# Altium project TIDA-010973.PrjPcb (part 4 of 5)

## Sheet TIDA-010973_JTAG_UART.SchDoc
size 558 x 431 mm; Date: Not shown in title block; ApprovedBy: Not shown in title block; CheckedBy: Not shown in title block; Author: Not shown in title block; CompanyName: Not shown in title block; Engineer: Not shown in title block; Organization: Not shown in title block; Address1: Not shown in title block; Address2: Not shown in title block; Address3: Not shown in title block; Address4: Not shown in title block; DocumentNumber: 2; Revision: Use project parameter SCH_Rev; SheetNumber: 14; SheetTotal: 15
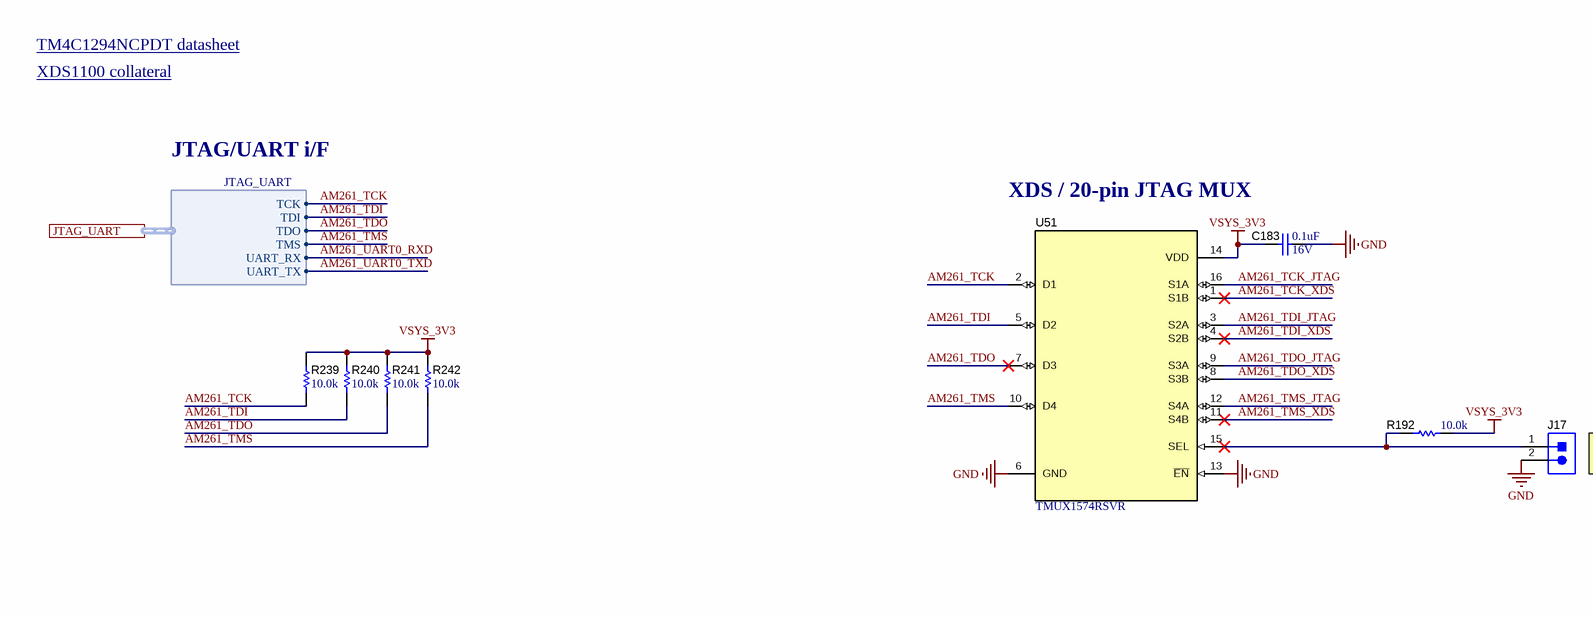
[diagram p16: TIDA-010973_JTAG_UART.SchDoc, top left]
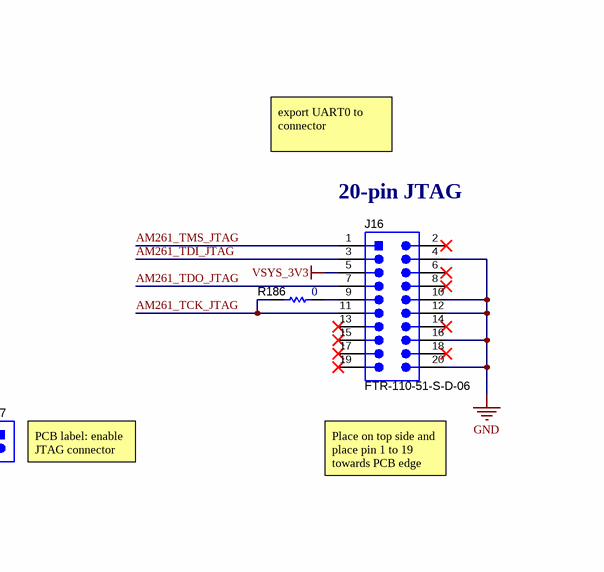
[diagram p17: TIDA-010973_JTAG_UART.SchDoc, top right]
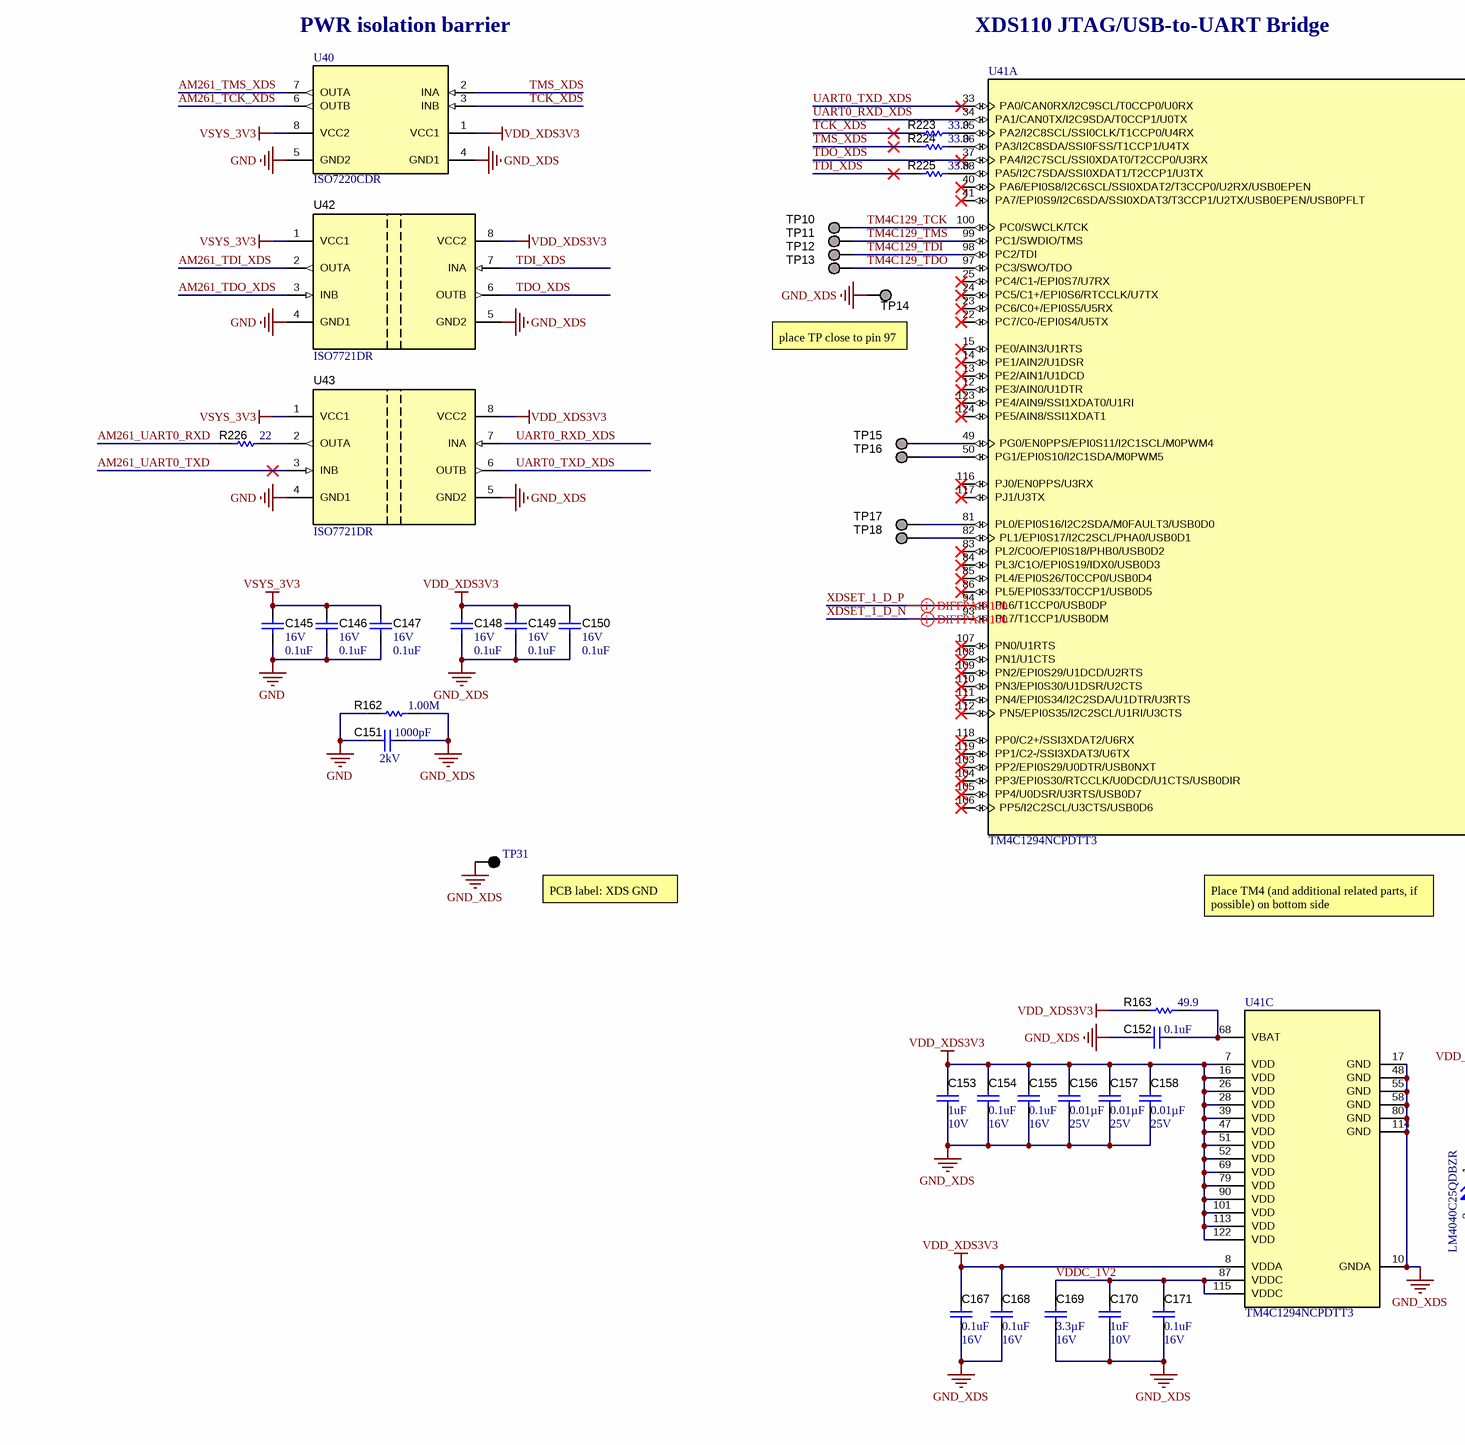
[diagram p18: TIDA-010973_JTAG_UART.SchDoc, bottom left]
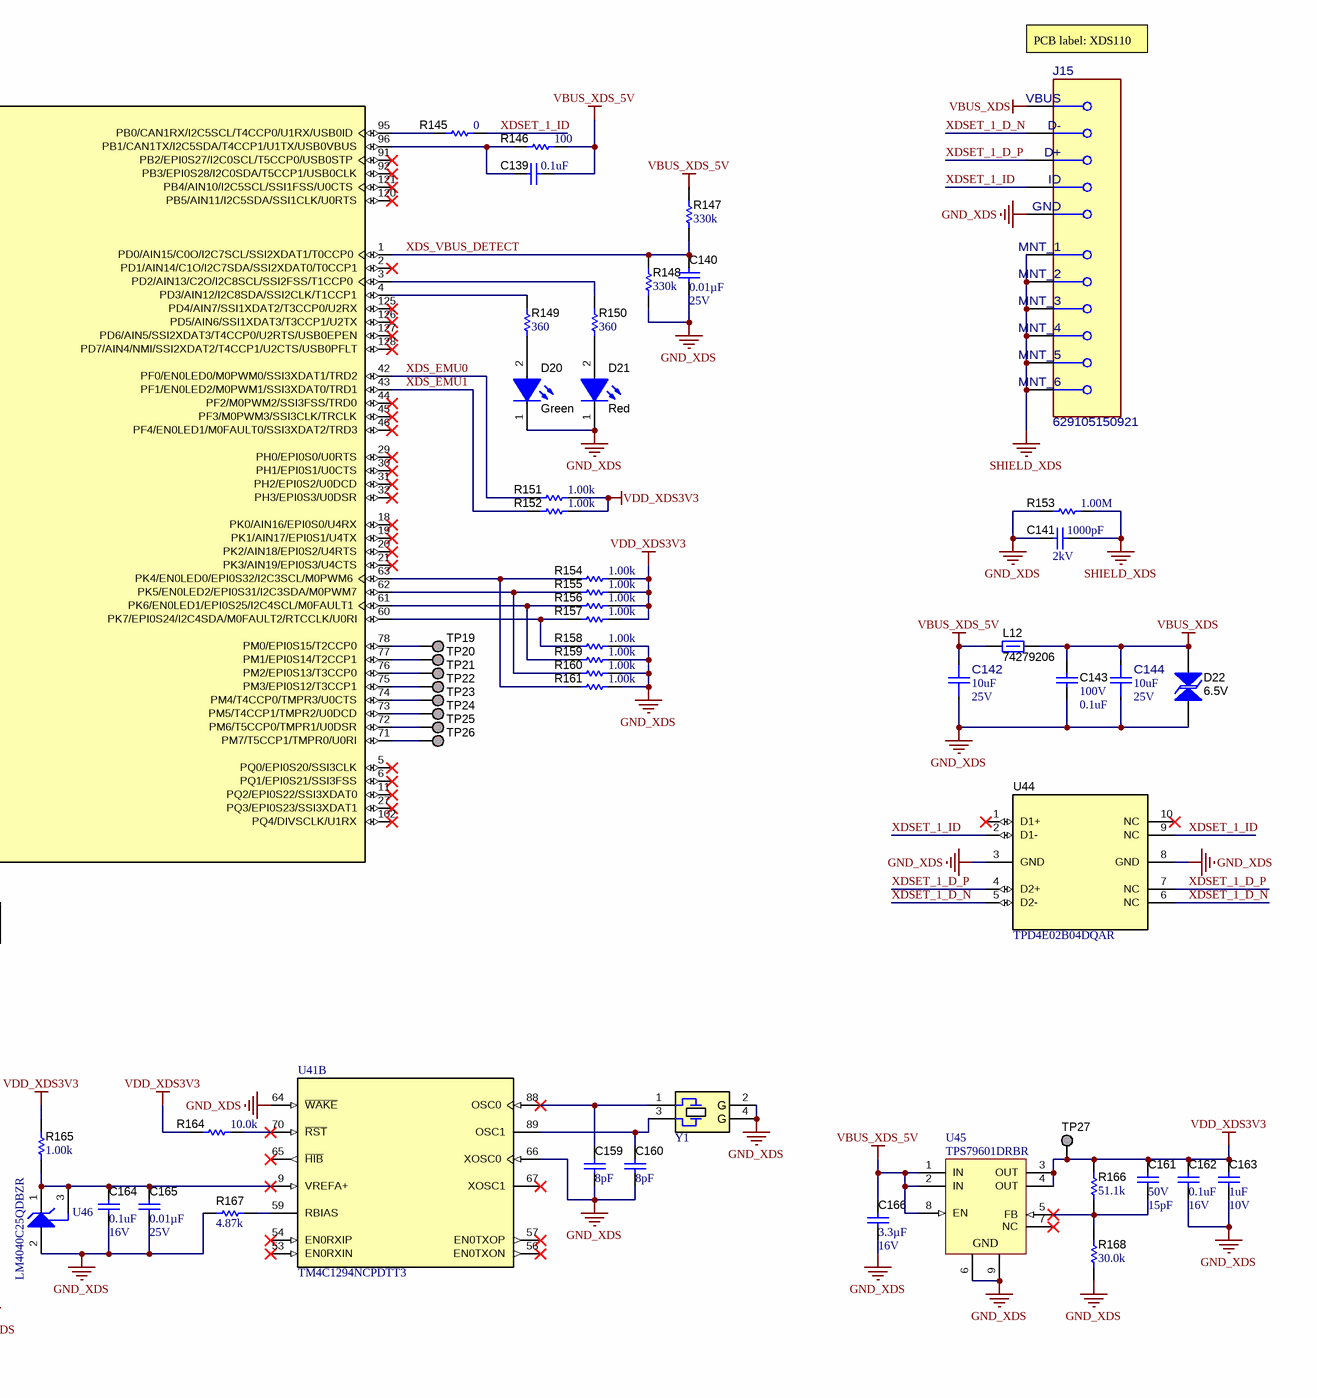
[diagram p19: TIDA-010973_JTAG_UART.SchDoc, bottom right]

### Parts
C139  ValueDisplayed: 0.1uF  [0402L]  (hidden comment: 885012205037)
C140  ValueDisplayed: 0.01µF  VDC_V: 25V  [0402L]  (hidden comment: 04023C103JAT2A)
C141  VDC_V: 2kV  ValueDisplayed: 1000pF  [1812_254]  (hidden comment: 1812GC102KA1)
C142  ValueDisplayed: 10uF  VDC_V: 25V  [FP-885012106031_0603-IPC_C]  (hidden comment: 885012106031)
C143  VDC_V: 100V  ValueDisplayed: 0.1uF  [0402L]  (hidden comment: GRM155R62A104KE14D)
C144  ValueDisplayed: 10uF  VDC_V: 25V  [FP-885012106031_0603-IPC_C]  (hidden comment: 885012106031)
C145  VDC_V: 16V  ValueDisplayed: 0.1uF  [0402L]  (hidden comment: 885012205037)
C146  VDC_V: 16V  ValueDisplayed: 0.1uF  [0402L]  (hidden comment: 885012205037)
C147  VDC_V: 16V  ValueDisplayed: 0.1uF  [0402L]  (hidden comment: 885012205037)
C148  VDC_V: 16V  ValueDisplayed: 0.1uF  [0402L]  (hidden comment: 885012205037)
C149  VDC_V: 16V  ValueDisplayed: 0.1uF  [0402L]  (hidden comment: 885012205037)
C150  VDC_V: 16V  ValueDisplayed: 0.1uF  [0402L]  (hidden comment: 885012205037)
C151  VDC_V: 2kV  ValueDisplayed: 1000pF  [1812_254]  (hidden comment: 1812GC102KA1)
C152  ValueDisplayed: 0.1uF  [0402L]  (hidden comment: 885012205037)
C153  VDC_V: 10V  ValueDisplayed: 1uF  [0402L]  (hidden comment: 885012105012)
C154  VDC_V: 16V  ValueDisplayed: 0.1uF  [0402L]  (hidden comment: 885012205037)
C155  VDC_V: 16V  ValueDisplayed: 0.1uF  [0402L]  (hidden comment: 885012205037)
C156  ValueDisplayed: 0.01µF  VDC_V: 25V  [0402L]  (hidden comment: 04023C103JAT2A)
C157  ValueDisplayed: 0.01µF  VDC_V: 25V  [0402L]  (hidden comment: 04023C103JAT2A)
C158  ValueDisplayed: 0.01µF  VDC_V: 25V  [0402L]  (hidden comment: 04023C103JAT2A)
C159  Cap_F: 8pF  [0402L]  (hidden comment: GCM1555C1H8R0DA16D)
C160  Cap_F: 8pF  [0402L]  (hidden comment: GCM1555C1H8R0DA16D)
C161  VDC_V: 50V  ValueDisplayed: 15pF  [0402L]  (hidden comment: 885012005056)
C162  VDC_V: 16V  ValueDisplayed: 0.1uF  [0402L]  (hidden comment: 885012205037)
C163  VDC_V: 10V  ValueDisplayed: 1uF  [0402L]  (hidden comment: 885012105012)
C164  VDC_V: 16V  ValueDisplayed: 0.1uF  [0402L]  (hidden comment: 885012205037)
C165  ValueDisplayed: 0.01µF  VDC_V: 25V  [0402L]  (hidden comment: 04023C103JAT2A)
C166  Cap_F: 3.3µF  VDC_V: 16V  [0805_HV]  (hidden comment: C2012X7R1C335K125AB)
C167  VDC_V: 16V  ValueDisplayed: 0.1uF  [0402L]  (hidden comment: 885012205037)
C168  VDC_V: 16V  ValueDisplayed: 0.1uF  [0402L]  (hidden comment: 885012205037)
C169  Cap_F: 3.3µF  VDC_V: 16V  [0805L]  (hidden comment: C2012X7R1C335K125AB)
C170  VDC_V: 10V  ValueDisplayed: 1uF  [0402L]  (hidden comment: 885012105012)
C171  VDC_V: 16V  ValueDisplayed: 0.1uF  [0402L]  (hidden comment: 885012205037)
C183  VDC_V: 16V  ValueDisplayed: 0.1uF  [0402L]  (hidden comment: 885012205037)
D20  value Green  [WL-SMCW_GREEN]  (hidden comment: 150060VS75000)
D21  value Red  [WL-SMCW_RED]  (hidden comment: 150060RS75000)
D22  value 6.5V  [SMB-Bi]  (hidden comment: SMBJ6.5CA)
J15  629105150921  [FP-629105150921_CONN_PTH_USB_8MM0_5MM6-MFG]
J16  FTR-110-51-S-D-06  [Samtec_FTR-110-51-x-D-06]
J17  61300211121  [WURTH_61300211121]  (value not drawn)
L12  74279206  [0805L]
R145  ValueDisplayed: 0  [0402L]  (hidden comment: CRCW04020000Z0ED)
R146  ValueDisplayed: 100  [0402L]  (hidden comment: CRCW0402100RFKED)
R147  ValueDisplayed: 330k  [0402L]  (hidden comment: CRCW0402330KFKED)
R148  ValueDisplayed: 330k  [0402L]  (hidden comment: CRCW0402330KFKED)
R149  ValueDisplayed: 360  [0402L]  (hidden comment: CRCW0402360RJNED)
R150  ValueDisplayed: 360  [0402L]  (hidden comment: CRCW0402360RJNED)
R151  ValueDisplayed: 1.00k  [0402L]  (hidden comment: CRCW04021K00FKED)
R152  ValueDisplayed: 1.00k  [0402L]  (hidden comment: CRCW04021K00FKED)
R153  ValueDisplayed: 1.00M  [2010]  (hidden comment: CRCW20101M00FKEF)
R154  ValueDisplayed: 1.00k  [0402L]  (hidden comment: CRCW04021K00FKED)
R155  ValueDisplayed: 1.00k  [0402L]  (hidden comment: CRCW04021K00FKED)
R156  ValueDisplayed: 1.00k  [0402L]  (hidden comment: CRCW04021K00FKED)
R157  ValueDisplayed: 1.00k  [0402L]  (hidden comment: CRCW04021K00FKED)
R158  ValueDisplayed: 1.00k  [0402L]  (hidden comment: CRCW04021K00FKED)
R159  ValueDisplayed: 1.00k  [0402L]  (hidden comment: CRCW04021K00FKED)
R160  ValueDisplayed: 1.00k  [0402L]  (hidden comment: CRCW04021K00FKED)
R161  ValueDisplayed: 1.00k  [0402L]  (hidden comment: CRCW04021K00FKED)
R162  ValueDisplayed: 1.00M  [2010]  (hidden comment: CRCW20101M00FKEF)
R163  ValueDisplayed: 49.9  [0402L]  (hidden comment: CRCW040249R9FKED)
R164  ValueDisplayed: 10.0k  [0402L]  (hidden comment: CRCW040210K0FKED)
R165  ValueDisplayed: 1.00k  [0402L]  (hidden comment: CRCW04021K00FKED)
R166  ValueDisplayed: 51.1k  [0402L]  (hidden comment: CRCW040251K1FKED)
R167  ValueDisplayed: 4.87k  [0402L]  (hidden comment: CRCW04024K87FKED)
R168  ValueDisplayed: 30.0k  [0402L]  (hidden comment: CRCW040230K0FKED)
R186  ValueDisplayed: 0  [0402L]  (hidden comment: CRCW04020000Z0ED)
R192  ValueDisplayed: 10.0k  [0402L]  (hidden comment: CRCW040210K0FKED)
R223  ValueDisplayed: 33.0  [0402L]  (hidden comment: RMCF0402FT33R0)
R224  ValueDisplayed: 33.0  [0402L]  (hidden comment: RMCF0402FT33R0)
R225  ValueDisplayed: 33.0  [0402L]  (hidden comment: RMCF0402FT33R0)
R226  ValueDisplayed: 22  [0201]  (hidden comment: RC0201JR-0722RL)
R239  ValueDisplayed: 10.0k  [0402L]  (hidden comment: CRCW040210K0FKED)
R240  ValueDisplayed: 10.0k  [0402L]  (hidden comment: CRCW040210K0FKED)
R241  ValueDisplayed: 10.0k  [0402L]  (hidden comment: CRCW040210K0FKED)
R242  ValueDisplayed: 10.0k  [0402L]  (hidden comment: CRCW040210K0FKED)
TP10  TESTPOINT  [TP_25MIL-SMT]  (value not drawn)  (no BOM)
TP11  TESTPOINT  [TP_25MIL-SMT]  (value not drawn)  (no BOM)
TP12  TESTPOINT  [TP_25MIL-SMT]  (value not drawn)  (no BOM)
TP13  TESTPOINT  [TP_25MIL-SMT]  (value not drawn)  (no BOM)
TP14  TESTPOINT  [TP_25MIL-SMT]  (value not drawn)  (no BOM)
TP15  TESTPOINT  [TP_25MIL-SMT]  (value not drawn)  (no BOM)
TP16  TESTPOINT  [TP_25MIL-SMT]  (value not drawn)  (no BOM)
TP17  TESTPOINT  [TP_25MIL-SMT]  (value not drawn)  (no BOM)
TP18  TESTPOINT  [TP_25MIL-SMT]  (value not drawn)  (no BOM)
TP19  TESTPOINT  [TP_25MIL-SMT]  (value not drawn)  (no BOM)
TP20  TESTPOINT  [TP_25MIL-SMT]  (value not drawn)  (no BOM)
TP21  TESTPOINT  [TP_25MIL-SMT]  (value not drawn)  (no BOM)
TP22  TESTPOINT  [TP_25MIL-SMT]  (value not drawn)  (no BOM)
TP23  TESTPOINT  [TP_25MIL-SMT]  (value not drawn)  (no BOM)
TP24  TESTPOINT  [TP_25MIL-SMT]  (value not drawn)  (no BOM)
TP25  TESTPOINT  [TP_25MIL-SMT]  (value not drawn)  (no BOM)
TP26  TESTPOINT  [TP_25MIL-SMT]  (value not drawn)  (no BOM)
TP27  TESTPOINT  [TP_25MIL-SMT]  (value not drawn)  (no BOM)
TP31  5011  [Keystone5011]  (value not drawn)
U40  ISO7220CDR  [D0008B_N]
U41  TM4C1294NCPDTT3  [PDT0128A]  (parts A,B,C of 3)
U42  ISO7721DR  [D0008B_HV]
U43  ISO7721DR  [D0008B_HV]
U44  TPD4E02B04DQAR  [DQA0010A]
U45  TPS79601DRBR  [DRB0008B]
U46  LM4040C25QDBZR  [DBZ0003A_N]
U51  TMUX1574RSVR  [RSV0016A]
Y1  NX3225GA-16.000M-STD-CRG-1  [NDK_NX3225GA]  (value not drawn)

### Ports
JTAG_UART (harness JTAG_UART)

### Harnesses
JTAG_UART: TDI, TDO, TCK, TMS, UART_RX, UART_TX

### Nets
GND: C145.2 C146.2 C147.2 C151.2 C183.2 J16.4 J16.10 J16.12 J16.16 J16.20 J17.2 R162.1 U40.5(GND2) U42.4(GND1) U43.4(GND1) U51.6(GND) U51.13(~{EN})
GND_XDS: C140.2 C141.2 C142.1 C143.2 C144.1 C148.2 C149.2 C150.2 C151.1 C152.1 C153.2 C154.2 C155.2 C156.2 C157.2 C158.2 C159.2 C160.2 C162.2 C163.2 C164.2 C165.2 C166.2 C167.2 C168.2 C169.2 C170.2 C171.2 D20.1(K) D21.1(K) D22.1 J15.5(GND) R148.1 R153.1 R158.1 R159.1 R160.1 R161.1 R162.2 R167.1 R168.1 TP14.1 TP31.1 U40.4(GND1) U41.10(GNDA) U41.17(GND) U41.48(GND) U41.55(GND) U41.58(GND) U41.64(~{WAKE}) U41.66(XOSC0) U41.80(GND) U41.114(GND) U42.5(GND2) U43.5(GND2) U44.3(GND) U44.8(GND) U45.6(GND) U45.9(GND) U46.2(ANODE) Y1.2(GND) Y1.4(GND)
SHIELD_XDS: C141.1 J15.6(MNT_1) J15.7(MNT_2) J15.8(MNT_3) J15.9(MNT_4) J15.10(MNT_5) J15.11(MNT_6) R153.2
VBUS_XDS: C143.1 C144.2 D22.2 J15.1(VBUS) L12.2
VBUS_XDS_5V: C139.2 C142.2 C166.1 L12.1 R146.2 R147.2 U45.1(IN) U45.2(IN) U45.8(EN)
VDD_XDS3V3: C148.1 C149.1 C150.1 C153.1 C154.1 C155.1 C156.1 C157.1 C158.1 C161.1 C162.1 C163.1 C167.1 C168.1 R151.1 R152.1 R154.1 R155.1 R156.1 R157.1 R163.1 R164.1 R165.2 R166.2 TP27.1 U40.1(VCC1) U41.7(VDD) U41.8(VDDA) U41.16(VDD) U41.26(VDD) U41.28(VDD) U41.39(VDD) U41.47(VDD) U41.51(VDD) U41.52(VDD) U41.69(VDD) U41.79(VDD) U41.90(VDD) U41.101(VDD) U41.113(VDD) U41.122(VDD) U42.8(VCC2) U43.8(VCC2) U45.3(OUT) U45.4(OUT)
VSYS_3V3: C145.1 C146.1 C147.1 C183.1 J16.5 R192.2 R239.2 R240.2 R241.2 R242.2 U40.8(VCC2) U42.1(VCC1) U43.1(VCC1) U51.14(VDD)
AM261_TCK: R239.1 U51.2(D1) ; port JTAG_UART.TCK
AM261_TCK_JTAG: J16.11 R186.1 U51.16(S1A)
AM261_TCK_XDS: U40.6(OUTB) U51.1(S1B)
AM261_TDI: R240.1 U51.5(D2) ; port JTAG_UART.TDI
AM261_TDI_JTAG: J16.3 U51.3(S2A)
AM261_TDI_XDS: U42.2(OUTA) U51.4(S2B)
AM261_TDO: R241.1 U51.7(D3) ; port JTAG_UART.TDO
AM261_TDO_JTAG: J16.7 U51.9(S3A)
AM261_TDO_XDS: U42.3(INB) U51.8(S3B)
AM261_TMS: R242.1 U51.10(D4) ; port JTAG_UART.TMS
AM261_TMS_JTAG: J16.1 U51.12(S4A)
AM261_TMS_XDS: U40.7(OUTA) U51.11(S4B)
AM261_UART0_RXD: R226.1 ; port JTAG_UART.UART_RX
AM261_UART0_TXD: U43.3(INB) ; port JTAG_UART.UART_TX
TCK_XDS: R223.1 U40.3(INB)
TDI_XDS: R225.1 U42.7(INA)
TDO_XDS: U41.37(PA4/I2C7SCL/SSI0XDAT0/T2CCP0/U3RX) U42.6(OUTB)
TM4C129_TCK: TP10.1 U41.100(PC0/SWCLK/TCK)
TM4C129_TDI: TP12.1 U41.98(PC2/TDI)
TM4C129_TDO: TP13.1 U41.97(PC3/SWO/TDO)
TM4C129_TMS: TP11.1 U41.99(PC1/SWDIO/TMS)
TMS_XDS: R224.1 U40.2(INA)
UART0_RXD_XDS: U41.34(PA1/CAN0TX/I2C9SDA/T0CCP1/U0TX) U43.7(INA)
UART0_TXD_XDS: U41.33(PA0/CAN0RX/I2C9SCL/T0CCP0/U0RX) U43.6(OUTB)
VDDC_1V2: C169.1 C170.1 C171.1 U41.87(VDDC) U41.115(VDDC)
XDS_EMU0: R151.2 U41.42(PF0/EN0LED0/M0PWM0/SSI3XDAT1/TRD2)
XDS_EMU1: R152.2 U41.43(PF1/EN0LED2/M0PWM1/SSI3XDAT0/TRD1)
XDS_VBUS_DETECT: C140.1 R147.1 R148.2 U41.1(PD0/AIN15/C0O/I2C7SCL/SSI2XDAT1/T0CCP0)
XDSET_1_D_N: J15.2(D-) U41.93(PL7/T1CCP1/USB0DM) U44.5(D2-) U44.6(NC)
XDSET_1_D_P: J15.3(D+) U41.94(PL6/T1CCP0/USB0DP) U44.4(D2+) U44.7(NC)
XDSET_1_ID: J15.4(ID) R145.2 U44.2(D1-) U44.9(NC)
NetC139_1: C139.1 R146.1 U41.96(PB1/CAN1TX/I2C5SDA/T4CCP1/U1TX/USB0VBUS)
NetC152_2: C152.2 R163.2 U41.68(VBAT)
NetC159_1: C159.1 U41.88(OSC0) Y1.1
NetC160_1: C160.1 U41.89(OSC1) Y1.3
NetC161_2: C161.2 R166.1 R168.2 U45.5(FB)
NetC164_1: C164.1 C165.1 R165.1 U41.9(VREFA+) U46.1(CATHODE) U46.3(NC)
NetD20_2: D20.2(A) R149.1
NetD21_2: D21.2(A) R150.1
NetJ16_9: J16.9 R186.2
NetJ17_1: J17.1 R192.1 U51.15(SEL)
NetR145_1: R145.1 U41.95(PB0/CAN1RX/I2C5SCL/T4CCP0/U1RX/USB0ID)
NetR149_2: R149.2 U41.4(PD3/AIN12/I2C8SDA/SSI2CLK/T1CCP1)
NetR150_2: R150.2 U41.3(PD2/AIN13/C2O/I2C8SCL/SSI2FSS/T1CCP0)
NetR154_2: R154.2 R161.2 U41.63(PK4/EN0LED0/EPI0S32/I2C3SCL/M0PWM6)
NetR155_2: R155.2 R160.2 U41.62(PK5/EN0LED2/EPI0S31/I2C3SDA/M0PWM7)
NetR156_2: R156.2 R159.2 U41.61(PK6/EN0LED1/EPI0S25/I2C4SCL/M0FAULT1)
NetR157_2: R157.2 R158.2 U41.60(PK7/EPI0S24/I2C4SDA/M0FAULT2/RTCCLK/U0RI)
NetR164_2: R164.2 U41.70(~{RST})
NetR167_2: R167.2 U41.59(RBIAS)
NetR223_2: R223.2 U41.35(PA2/I2C8SCL/SSI0CLK/T1CCP0/U4RX)
NetR224_2: R224.2 U41.36(PA3/I2C8SDA/SSI0FSS/T1CCP1/U4TX)
NetR225_2: R225.2 U41.38(PA5/I2C7SDA/SSI0XDAT1/T2CCP1/U3TX)
NetR226_2: R226.2 U43.2(OUTA)
NetTP15_1: TP15.1 U41.49(PG0/EN0PPS/EPI0S11/I2C1SCL/M0PWM4)
NetTP16_1: TP16.1 U41.50(PG1/EPI0S10/I2C1SDA/M0PWM5)
NetTP17_1: TP17.1 U41.81(PL0/EPI0S16/I2C2SDA/M0FAULT3/USB0D0)
NetTP18_1: TP18.1 U41.82(PL1/EPI0S17/I2C2SCL/PHA0/USB0D1)
NetTP19_1: TP19.1 U41.78(PM0/EPI0S15/T2CCP0)
NetTP20_1: TP20.1 U41.77(PM1/EPI0S14/T2CCP1)
NetTP21_1: TP21.1 U41.76(PM2/EPI0S13/T3CCP0)
NetTP22_1: TP22.1 U41.75(PM3/EPI0S12/T3CCP1)
NetTP23_1: TP23.1 U41.74(PM4/T4CCP0/TMPR3/U0CTS)
NetTP24_1: TP24.1 U41.73(PM5/T4CCP1/TMPR2/U0DCD)
NetTP25_1: TP25.1 U41.72(PM6/T5CCP0/TMPR1/U0DSR)
NetTP26_1: TP26.1 U41.71(PM7/T5CCP1/TMPR0/U0RI)

Not connected (* = marked no-connect by the designer): J16 2* 6* 8* 13* 14* 15* 17* 18* 19*; U41 2(PD1/AIN14/C1O/I2C7SDA/SSI2XDAT0/T0CCP1)* 5(PQ0/EPI0S20/SSI3CLK)* 6(PQ1/EPI0S21/SSI3FSS)* 11(PQ2/EPI0S22/SSI3XDAT0)* 12(PE3/AIN0/U1DTR)* 13(PE2/AIN1/U1DCD)* 14(PE1/AIN2/U1DSR)* 15(PE0/AIN3/U1RTS)* 18(PK0/AIN16/EPI0S0/U4RX)* 19(PK1/AIN17/EPI0S1/U4TX)* 20(PK2/AIN18/EPI0S2/U4RTS)* 21(PK3/AIN19/EPI0S3/U4CTS)* 22(PC7/C0-/EPI0S4/U5TX)* 23(PC6/C0+/EPI0S5/U5RX)* 24(PC5/C1+/EPI0S6/RTCCLK/U7TX)* 25(PC4/C1-/EPI0S7/U7RX)* 27(PQ3/EPI0S23/SSI3XDAT1)* 29(PH0/EPI0S0/U0RTS)* 30(PH1/EPI0S1/U0CTS)* 31(PH2/EPI0S2/U0DCD)* 32(PH3/EPI0S3/U0DSR)* 40(PA6/EPI0S8/I2C6SCL/SSI0XDAT2/T3CCP0/U2RX/USB0EPEN)* 41(PA7/EPI0S9/I2C6SDA/SSI0XDAT3/T3CCP1/U2TX/USB0EPEN/USB0PFLT)* 44(PF2/M0PWM2/SSI3FSS/TRD0)* 45(PF3/M0PWM3/SSI3CLK/TRCLK)* 46(PF4/EN0LED1/M0FAULT0/SSI3XDAT2/TRD3)* 53(EN0RXIN)* 54(EN0RXIP)* 56(EN0TXON)* 57(EN0TXOP)* 65(~{HIB})* 67(XOSC1)* 83(PL2/C0O/EPI0S18/PHB0/USB0D2)* 84(PL3/C1O/EPI0S19/IDX0/USB0D3)* 85(PL4/EPI0S26/T0CCP0/USB0D4)* 86(PL5/EPI0S33/T0CCP1/USB0D5)* 91(PB2/EPI0S27/I2C0SCL/T5CCP0/USB0STP)* 92(PB3/EPI0S28/I2C0SDA/T5CCP1/USB0CLK)* 102(PQ4/DIVSCLK/U1RX)* 103(PP2/EPI0S29/U0DTR/USB0NXT)* 104(PP3/EPI0S30/RTCCLK/U0DCD/U1CTS/USB0DIR)* 105(PP4/U0DSR/U3RTS/USB0D7)* 106(PP5/I2C2SCL/U3CTS/USB0D6)* 107(PN0/U1RTS)* 108(PN1/U1CTS)* 109(PN2/EPI0S29/U1DCD/U2RTS)* 110(PN3/EPI0S30/U1DSR/U2CTS)* 111(PN4/EPI0S34/I2C2SDA/U1DTR/U3RTS)* 112(PN5/EPI0S35/I2C2SCL/U1RI/U3CTS)* 116(PJ0/EN0PPS/U3RX)* 117(PJ1/U3TX)* 118(PP0/C2+/SSI3XDAT2/U6RX)* 119(PP1/C2-/SSI3XDAT3/U6TX)* 120(PB5/AIN11/I2C5SDA/SSI1CLK/U0RTS)* 121(PB4/AIN10/I2C5SCL/SSI1FSS/U0CTS)* 123(PE4/AIN9/SSI1XDAT0/U1RI)* 124(PE5/AIN8/SSI1XDAT1)* 125(PD4/AIN7/SSI1XDAT2/T3CCP0/U2RX)* 126(PD5/AIN6/SSI1XDAT3/T3CCP1/U2TX)* 127(PD6/AIN5/SSI2XDAT3/T4CCP0/U2RTS/USB0EPEN)* 128(PD7/AIN4/NMI/SSI2XDAT2/T4CCP1/U2CTS/USB0PFLT)*; U44 1(D1+)* 10(NC)*; U45 7(NC)*

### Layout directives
differential pair: XDSET_1_D_N, XDSET_1_D_P

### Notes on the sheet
- TM4C1294NCPDT datasheet <https://www.ti.com/lit/ds/symlink/tm4c1294ncpdt.pdf>
- XDS1100 collateral <https://software-dl.ti.com/ccs/esd/documents/xdsdebugprobes/emu_xds110.html>
- JTAG/UART i/F
- export UART0 to connector
- XDS / 20-pin JTAG MUX
- (near J16) 20-pin JTAG
- (near J17) PCB label: enable JTAG connector
- Place on top side and place pin 1 to 19 towards PCB edge
- PCB label: XDS110
- PWR isolation barrier
- XDS110 JTAG/USB-to-UART Bridge
- (near TP14) place TP close to pin 97
- PCB label: XDS GND
- Place TM4 (and additional related parts, if  possible) on bottom side

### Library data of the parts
C139 C152 = CMP-0006228-2: CAP, CERM, 0.1 uF, 16 V, +/- 10%, X7R, 0402; Manufacturer: Wurth Elektronik; TaMin_C: -55°C; Polarized: N; SizeAreaWB_mm2: 3; Value1: Unknown; U/M: EA; Value: 0.1uF; TaMax_C: 125°C; SizeZ_mm: 0.6; SizeX_mm: 1; SizeY_mm: 0.5; Cap_Case: 0402; Value2: 16V; Cap_F: 100nF; AEC Category: Q200
C140 C156-C158 C165 = CMP-0085568-1: CAP, CERM, 0.01 µF, 25 V,+/- 5%, X7R, 0402; Manufacturer: AVX; AEC Category: Q200; SizeAreaWB_mm2: 3; SizeArea_mm2: 0.5; Polarized: N; TaMin_C: -55°C; Value: 0.01uF; U/M: EA; SizeX_mm: 1; Cap_Case: 0402; Cap_F: 10nF; SizeZ_mm: 0.6; TaMax_C: 125°C
C141 C151 = CMP-0009293-2: CAP, CERM, 1000 pF, 2000 V, +/- 10%, X7R, 1812; Manufacturer: AVX; TaMin_C: -55°C; Polarized: N; SizeAreaWB_mm2: 23.1; Value1: Unknown; U/M: EA; Value: 1000pF; TaMax_C: 125°C; SizeZ_mm: 2.54; SizeX_mm: 4.5; SizeY_mm: 3.2; Cap_Case: 1812; Value2: 2000V; SizeArea_mm2: 14.4; Cap_F: 1nF; AEC Category: Q200
C142 C144 = CMP-0096736-1: 10 µF ±20% 25V Ceramic Capacitor X5R 0603 (1608 Metric); Manufacturer: Wurth; Cap_F: 10µF; AEC Qualified: No; SizeZ_mm: 1mm; Value: 10µF; TempCo: 15%
C143 = CMP-0006618-2: CAP, CERM, 0.1 uF, 100 V, +/- 10%, X5R, 0402; Manufacturer: MuRata; TaMin_C: -55°C; Polarized: N; SizeAreaWB_mm2: 3; Value1: Unknown; U/M: EA; Value: 0.1uF; TaMax_C: 85°C; SizeZ_mm: 0.6; SizeX_mm: 1; SizeY_mm: 0.5; Cap_Case: 0402; Cap_F: 100nF; AEC Category: Q200
C145-C150 C154 C155 C162 C164 C167 C168 C171 C183 = CMP-0006228-2: CAP, CERM, 0.1 uF, 16 V, +/- 10%, X7R, 0402; Manufacturer: Wurth Elektronik; TaMin_C: -55°C; Polarized: N; SizeAreaWB_mm2: 3; Value1: Unknown; U/M: EA; Value: 0.1uF; TaMax_C: 125°C; SizeZ_mm: 0.6; SizeX_mm: 1; SizeY_mm: 0.5; Cap_Case: 0402; Cap_F: 100nF; AEC Category: Q200
C153 C163 C170 = CMP-0064924-2: CAP, CERM, 1 uF, 10 V,+/- 20%, X5R, 0402; Manufacturer: Wurth Elektronik; TaMin_C: -55°C; Polarized: N; SizeAreaWB_mm2: 3; Value1: Unknown; U/M: EA; Value: 1uF; TaMax_C: 85°C; SizeZ_mm: 0.6; SizeX_mm: 1; SizeY_mm: 0.5; Cap_Case: 0402; Cap_F: 1µF; AEC Category: Q200
C159 C160 = CMP-0087060-3: Cap Ceramic 8pF 50V C0G 0.5pF SMD 0402 125C Paper T/R; Manufacturer: Murata Electronics North America; AEC Qualified: Yes; TempCo: 30ppm/°C; AEC Grade: Grade 1; SizeZ_mm: 0.55mm
C161 = CMP-0006216-2: CAP, CERM, 15 pF, 50 V, +/- 5%, C0G/NP0, 0402; Manufacturer: Wurth Elektronik; TaMin_C: -55°C; Polarized: N; SizeAreaWB_mm2: 3; Value1: Unknown; U/M: EA; Value: 15pF; TaMax_C: 125°C; SizeZ_mm: 0.6; SizeX_mm: 1; SizeY_mm: 0.5; Cap_Case: 0402; AEC Category: Q200
C166 C169 = CMP-0860551-1: CAP, CERM, 3.3 µF, 16 V,+/- 10%, X7R, 0805; Manufacturer: TDK; TaMax_C: 125°C; TaMin_C: -55°C; AEC Category: Q200; SizeArea_mm2: 2.5; Value: 3.3uF; U/M: EA; SizeX_mm: 2; Polarized: N; SizeY_mm: 1.25; SizeZ_mm: 1.45; Cap_Case: 0805; SizeAreaWB_mm2: 6.75
D20 = CMP-0002894-2: LED, Green, SMD; Manufacturer: Wurth Elektronik; Type: AlInGaP; Value2: 2V; Io_A: 20mA; Value1: W
D21 = CMP-0002947-3: LED, Red, SMD; Manufacturer: Wurth Elektronik; Value1: 0.072W; Vf_V: 2V; Angle: 140; Tjmax_C: 85°C; Type: AlInGaP; Vr_V: 5V; Io_A: 30mA; Power_TotalModule: 72mW
D22 = CMP-0005599-2: Diode, TVS, Bi, 6.5 V, SMB; Manufacturer: Littelfuse; SizeZ_mm: 2.6; SizeY_mm: 3.81; Ppk: 600W; AEC Category: Q101; RJA_CperW: 100; SizeArea_mm2: 21.336; SizeX_mm: 5.6; SizeAreaWB_mm2: 44.156
J15 = CMP-0097752-1: Conn Micro USB 2.0 Type AB RCP 5 POS 0.65mm Solder RA SMD 5 Terminal 1 Port T/R; Manufacturer: Wurth Electronics; Shrouded: true; Voltage_V: 30V; Usb Standard: USB 2.0; Current_A: 1A; ContactFinish: Gold; SizeZ_mm: 3.2mm; Is Female: yes; Conn Orientation: Horizontal; AEC Qualified: No
J16 = CMP-0075640-2: Header, 1.27mm, 10x2, Tin, SMT; Manufacturer: Samtec; Pitch_mm: 1.27; Gender: Male; Cert_UL: Y; Green_REACh: Passed; Current_A: 3.1A; Shrouded: N; RowSpacing_mm: 2.54; Green_Lifecycle: Active; Row_Count: 2
J17 = CMP-0054794-2: Header, 2.54 mm, 2x1, Gold, TH; Manufacturer: Wurth Elektronik; Shrouded: N; Gender: Male; Green_REACh: Passed; Pitch_mm: 2.54; Green_Lifecycle: Active; Row_Count: 1; Cert_UL: Y
L12 = CMP-0003091-1: Ferrite Bead, 30 ohm @ 100 MHz, 3 A, 0805; Manufacturer: Wurth Elektronik; Ztyp@1GHz_Ohm: 71.201; ZTyp@100MHz_Ohm: 30; SizeAreaWB_mm2: 6.75; DCR_ohm: 0.025; Value1: 0.025 ohm; Value: 30 ohm; Imax_A: 3A; SizeZ_mm: 1.45; SizeX_mm: 2; SizeY_mm: 1.25; SizeArea_mm2: 2.5
R145 R186 = CMP-0026822-3: RES, 0, 5%, 0.063 W, AEC-Q200 Grade 0, 0402; Manufacturer: Vishay-Dale; Power_W: 63mW; TempCo: 200 ppm/C; Value_Code: 0000; Value: 0; EIA_Code: E24; SizeX_mm: 1; SizeY_mm: 0.5; SizeZ_mm: 0.6; Value2: 0.063W; AEC Qualified: Y; VDC_V: 50V; AEC Category: Q200
R146 = CMP-0025951-3: RES, 100, 1%, 0.063 W, AEC-Q200 Grade 0, 0402; Manufacturer: Vishay-Dale; Power_W: 63mW; TempCo: 100 ppm/C; Value_Code: 100R; Value: 100; EIA_Code: E96; SizeX_mm: 1; SizeY_mm: 0.5; SizeZ_mm: 0.6; Value2: 0.063W; AEC Qualified: Y; VDC_V: 50V; AEC Category: Q200; AEC Grade: 0
R147 R148 = CMP-0078210-2: RES, 330 k, 1%, 0.063 W, AEC-Q200 Grade 0, 0402; Manufacturer: Vishay-Dale; SizeArea_mm2: 0.5; AEC Qualified: Y; AEC Category: Q200; Value: 330k; SizeZ_mm: 0.6; TempCo: 100 ppm/C; AEC Grade: 0; Power_W: 63mW; VDC_V: 50V; Value2: 0.063W; SizeX_mm: 1
R149 R150 = CMP-0026910-3: RES, 360, 5%, 0.063 W, AEC-Q200 Grade 0, 0402; Manufacturer: Vishay-Dale; Power_W: 63mW; TempCo: 200 ppm/C; Value_Code: 360R; Value: 360; EIA_Code: E24; SizeX_mm: 1; SizeY_mm: 0.5; SizeZ_mm: 0.6; Value2: 0.063W; AEC Qualified: Y; VDC_V: 50V; AEC Category: Q200; AEC Grade: 0
R151 R152 R154-R161 R165 = CMP-0026071-3: RES, 1.00 k, 1%, 0.063 W, AEC-Q200 Grade 0, 0402; Manufacturer: Vishay-Dale; Power_W: 63mW; TempCo: 100 ppm/C; Value_Code: 1k00; Value: 1.00k; EIA_Code: E96; Res_ohm: 1k; SizeX_mm: 1; SizeY_mm: 0.5; SizeZ_mm: 0.6; Value2: 0.063W; AEC Qualified: Y; VDC_V: 50V; AEC Category: Q200; AEC Grade: 0
R153 R162 = CMP-0016296-3: RES, 1.00 M, 1%, 0.75 W, AEC-Q200 Grade 0, 2010; Manufacturer: Vishay-Dale; Power_W: 750mW; TempCo: 100 ppm/C; Value_Code: 1M00; Value: 1.00Meg; EIA_Code: E96; Res_ohm: 1M; SizeX_mm: 5; SizeY_mm: 2.5; SizeZ_mm: 1.66; Value2: 0.75W; SizeArea_mm2: 12.5; AEC Qualified: Y; VDC_V: 400V; AEC Grade: 0; AEC Category: Q200
R163 = CMP-0026404-2: RES, 49.9, 1%, 0.063 W, AEC-Q200 Grade 0, 0402; Manufacturer: Vishay-Dale; Power_W: 63mW; TempCo: 100 ppm/C; Value_Code: 49R9; Value: 49.9; EIA_Code: E96; SizeX_mm: 1; SizeY_mm: 0.5; SizeZ_mm: 0.6; Value2: 0.063W; AEC Qualified: Y; VDC_V: 50V; AEC Category: Q200; AEC Grade: 0
R164 R192 R239-R242 = CMP-0025958-3: RES, 10.0 k, 1%, 0.063 W, AEC-Q200 Grade 0, 0402; Manufacturer: Vishay-Dale; Power_W: 63mW; TempCo: 100 ppm/C; Value_Code: 10k0; Value: 10.0k; EIA_Code: E96; Res_ohm: 10k; SizeX_mm: 1; SizeY_mm: 0.5; SizeZ_mm: 0.6; Value2: 0.063W; AEC Qualified: Y; VDC_V: 50V; AEC Category: Q200; AEC Grade: 0
R166 = CMP-0026437-2: RES, 51.1 k, 1%, 0.063 W, AEC-Q200 Grade 0, 0402; Manufacturer: Vishay-Dale; Power_W: 63mW; TempCo: 100 ppm/C; Value_Code: 51k1; Value: 51.1k; EIA_Code: E96; SizeX_mm: 1; SizeY_mm: 0.5; SizeZ_mm: 0.6; Value2: 0.063W; AEC Qualified: Y; VDC_V: 50V; AEC Category: Q200; AEC Grade: 0
R167 = CMP-0026413-2: RES, 4.87 k, 1%, 0.063 W, AEC-Q200 Grade 0, 0402; Manufacturer: Vishay-Dale; Power_W: 63mW; TempCo: 100 ppm/C; Value_Code: 4k87; Value: 4.87k; EIA_Code: E96; SizeX_mm: 1; SizeY_mm: 0.5; SizeZ_mm: 0.6; Value2: 0.063W; AEC Qualified: Y; VDC_V: 50V; AEC Category: Q200; AEC Grade: 0
R168 = CMP-0078244-2: RES, 30.0 k, 1%, 0.063 W, AEC-Q200 Grade 0, 0402; Manufacturer: Vishay-Dale; Power_W: 63mW; Green_Lifecycle: Active; TempCo: 100 ppm/C; Value_Code: 30k0; Green_REACh: Passed; Value: 30.0k; Res_ohm: 30k; SizeX_mm: 1; SizeY_mm: 0.5; SizeZ_mm: 0.6; Value2: 0.063W; AEC Qualified: Y; VDC_V: 50V; AEC Grade: 0; AEC Category: Q200
R223-R225 = CMP-0026759-1: RES, 33.0, 1%, 0.063 W, AEC-Q200 Grade 0, 0402; Manufacturer: Stackpole Electronics Inc; Power_W: 63mW; TempCo: 100 ppm/C; Value_Code: 33R0; U/M: EA; Value: 33.0; Res_ohm: 33; SizeX_mm: 1; SizeY_mm: 0.5; SizeZ_mm: 0.6; Value2: 0.063W; AEC Qualified: Y; VDC_V: 50V; AEC Grade: 0; AEC Category: Q200
R226 = CMP-0027074-3: RES, 22, 5%, 0.05 W, 0201; Manufacturer: Yageo America; Power_W: 50mW; TempCo: 200 ppm/C; Value_Code: 22R0; U/M: EA; Value: 22; EIA_Code: E24; SizeX_mm: 0.6; SizeY_mm: 0.3; SizeZ_mm: 0.26; Value2: 0.05W; SizeArea_mm2: 0.18; AEC Qualified: N; VDC_V: 25V; AEC Category: Q200
TP10-TP27 = CMP-0078143-4: TEST POINT.  No entry in BOM.
TP31 = CMP-0055148-2: Test Point, Multipurpose, Black, TH; Manufacturer: Keystone Electronics; CNHeader: FALSE; ContactFinish: Silver; Green_REACh: Passed; Green_Lifecycle: Active; CT: TRUE
U40 = CMP-0029369-1: 25 Mbps Dual Channels, 2 / 0, Digital Isolator, 3.3 V / 5 V, -40 to +125 degC, 8-pin SOIC (D), Green (RoHS & no Sb/Br); Manufacturer: Texas Instruments; Supply Voltage(s)(V): 3.3, 5; Prop Delay(Max)(ns): 42; Insulation Rating(VRMS): 2500; Datarate(Mbps): 25; TTL/CMOS Input Threshold: TTL; Rating: Catalog; Input Noise Filter: Yes
U41 = CMP-0029856-2: Tiva C Series Microcontroller, 1024 KB Flash, 256 KB SRAM, 12 Bit, 20 Channels, -40 to 105 degC, 128-Pin TQFP (PDT), Green (RoHS & no Sb/Br), Tray; Manufacturer: Texas Instruments; ADC Channels: 20; CPU: ARM Cortex-M4; Flash: 1024 KB; ADC Resolution: 12 Bits; Max Speed: 120 MHz; SRAM: 256 KB; SizeAreaWB_mm2: 324.0; SizeArea_mm2: 256.0; SizeX_mm: 16.0; SizeZ_mm: 1.2; CompType: IC
U42 U43 = CMP-0076059-2: High Speed, Robust EMC Dual-Channel Digital Isolator, D0008B (SOIC-8); Manufacturer: Texas Instruments; SizeY_mm: 4.9; SizeArea_mm2: 29.4; Rating: Catalog; CompType: IC; AEC Category: Q200; AEC Qualified: N; SizeZ_mm: 1.75; SizeAreaWB_mm2: 55.2; SizeX_mm: 6.0
U44 = CMP-0073612-3: 4-Channel ESD Protection Diode for USB Type-C and HDMI 2.0, DQA0010A (USON-10); Alternate Manufacturer: Texas Instruments; Green_Lifecycle: Active; SizeAreaWB_mm2: 7.0; Green_REACh: Passed; SizeZ_mm: 0.55; SizeX_mm: 1.0; SizeY_mm: 2.5; CompType: IC; AEC Category: Q200; AEC Qualified: Y
U45 = CMP-0036402-3: Single Output High PSRR LDO, 1 A, Adjustable 1.2 to 5.5 V Output, 2.7 to 5.5 V Input, 8-pin SON (DRB), -40 to 125 degC, Green (RoHS & no Sb/Br); Manufacturer: Texas Instruments; Vin(Min)(V): 2.7; Vout Adj(Max)(V): 5.5; Vout Adj(Min)(V): 1.2; Accuracy(%): 2; SubFamily: Single Channel LDO; Iq(Typ)(mA): 0.26; Vdo(Typ)(mV): 250; Iout(Max)(A): 1; AEC Category: Q200; AEC Qualified: N; CompType: IC; SizeAreaWB_mm2: 16.0; SizeArea_mm2: 9.0; SizeX_mm: 3.0; SizeZ_mm: 1.0
U46 = CMP-0033001-1: Precision Micropower Shunt Voltage Reference, 0.5% accuracy, 2.5 V, 15 ppm / degC, 15 mA, -40 to 125 degC, 3-pin SOT-23 (DBZ), Green (RoHS & no Sb/Br); Manufacturer: Texas Instruments; Initial Accuracy @ 25/deg C(%): 0.5; Temp Coeff(Typ)(ppm/ degree C): 15; Temp Coeff(Max)(ppm/ degree C): 100; Rating: Catalog; Min Iz for Regulation(uA): 75; VO(V): 2.5
U51 = CMP-0086167-3: Low-capacitance, 2:1 (SPDT) 4-channel, powered-off protection switch with 1.8 V logic, RSV0016A (UQFN-16); Manufacturer: Texas Instruments; SizeArea_mm2: 4.68; CompType: IC; AEC Qualified: N; SizeAreaWB_mm2: 10.08; SizeX_mm: 1.8; SizeZ_mm: 0.55; AEC Category: Q200; SizeY_mm: 2.6; Rating: Catalog
Y1 = CMP-0004635-3: Crystal, 16 MHz, 8pF, SMD; Manufacturer: NDK; TaMax_C: 70°C; TaMin_C: -10°C; Frequency Stability: +/-30ppm; Frequency_Fixed: 16MHz

## Sheet TIDA-010973_Memory.SchDoc
size 431 x 279 mm; Date: Not shown in title block; ApprovedBy: Not shown in title block; CheckedBy: Not shown in title block; Author: Not shown in title block; CompanyName: Not shown in title block; Engineer: Not shown in title block; Organization: Not shown in title block; Address1: Not shown in title block; Address2: Not shown in title block; Address3: Not shown in title block; Address4: Not shown in title block; DocumentNumber: 2; Revision: Use project parameter SCH_Rev; SheetNumber: 8; SheetTotal: 15; PageSetup: Record=PageOptions¦CenterHorizontal=True¦CenterVertical=True¦PrintScale=1.00¦XCorrection=1.00¦YCorrection=1.00¦PrintKind=0¦BorderSize=5000000¦LeftOffset=0¦BottomOffset=0¦Orientation=2¦PaperLength=1000¦PaperWidth=1000¦Scale=100¦PaperSource=15¦PrintQuality=600¦MediaType=1¦DitherType=10¦PaperKind=Letter¦PrintScaleMode=1
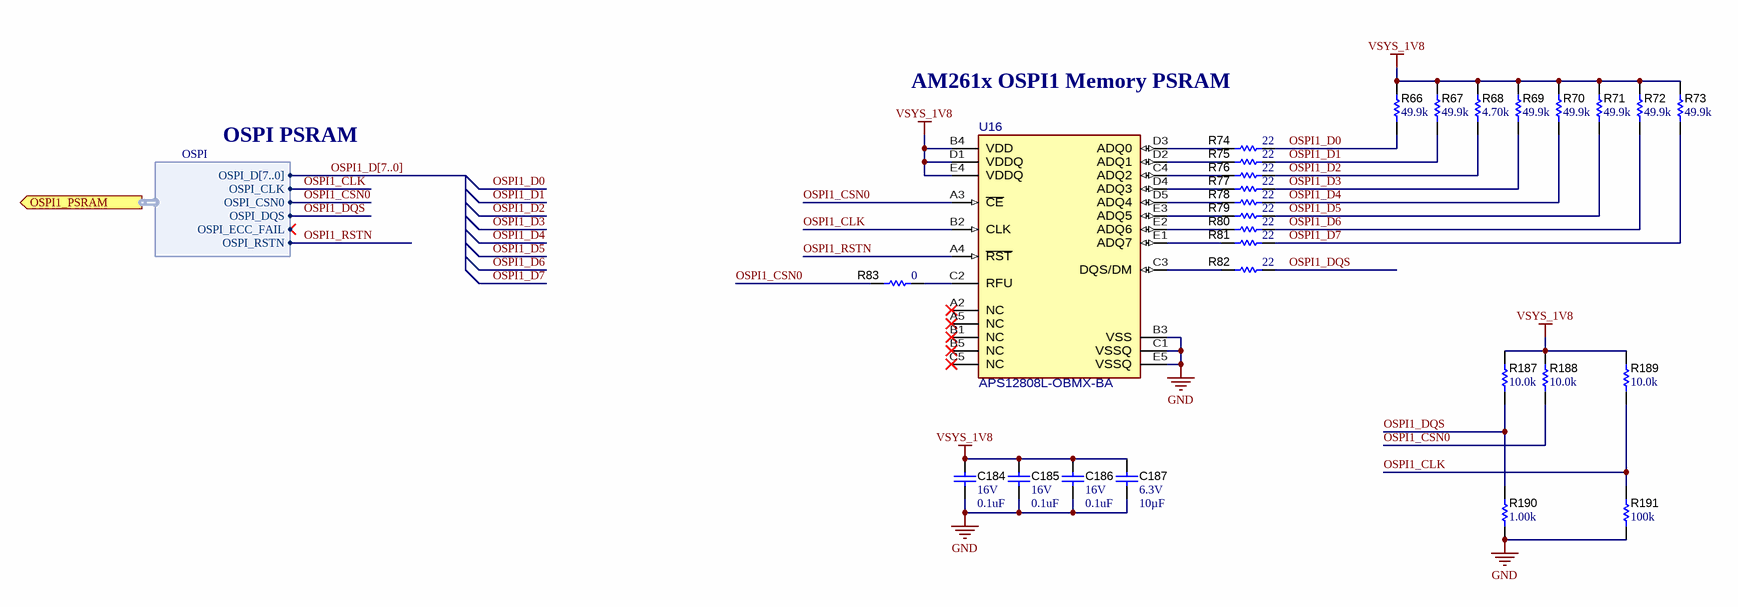
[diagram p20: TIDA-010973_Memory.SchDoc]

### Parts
C184  VDC_V: 16V  ValueDisplayed: 0.1uF  [0402L]  (hidden comment: 885012205037)
C185  VDC_V: 16V  ValueDisplayed: 0.1uF  [0402L]  (hidden comment: 885012205037)
C186  VDC_V: 16V  ValueDisplayed: 0.1uF  [0402L]  (hidden comment: 885012205037)
C187  VDC_V: 6.3V  ValueDisplayed: 10µF  [0402L]  (hidden comment: GRM155R60J106ME47D)
R66  ValueDisplayed: 49.9k  [0201L]  (hidden comment: RC0201FR-0749K9L)
R67  ValueDisplayed: 49.9k  [0201L]  (hidden comment: RC0201FR-0749K9L)
R68  ValueDisplayed: 4.70k  [0201_033L]  (hidden comment: CRCW02014K70FKED)
R69  ValueDisplayed: 49.9k  [0201L]  (hidden comment: RC0201FR-0749K9L)
R70  ValueDisplayed: 49.9k  [0201L]  (hidden comment: RC0201FR-0749K9L)
R71  ValueDisplayed: 49.9k  [0201L]  (hidden comment: RC0201FR-0749K9L)
R72  ValueDisplayed: 49.9k  [0201L]  (hidden comment: RC0201FR-0749K9L)
R73  ValueDisplayed: 49.9k  [0201L]  (hidden comment: RC0201FR-0749K9L)
R74  ValueDisplayed: 22  [0201L]  (hidden comment: RC0201JR-0722RL)
R75  ValueDisplayed: 22  [0201L]  (hidden comment: RC0201JR-0722RL)
R76  ValueDisplayed: 22  [0201L]  (hidden comment: RC0201JR-0722RL)
R77  ValueDisplayed: 22  [0201L]  (hidden comment: RC0201JR-0722RL)
R78  ValueDisplayed: 22  [0201L]  (hidden comment: RC0201JR-0722RL)
R79  ValueDisplayed: 22  [0201L]  (hidden comment: RC0201JR-0722RL)
R80  ValueDisplayed: 22  [0201L]  (hidden comment: RC0201JR-0722RL)
R81  ValueDisplayed: 22  [0201L]  (hidden comment: RC0201JR-0722RL)
R82  ValueDisplayed: 22  [0201L]  (hidden comment: RC0201JR-0722RL)
R83  ValueDisplayed: 0  [0201L]  (hidden comment: CRCW02010000Z0ED)
R187  ValueDisplayed: 10.0k  [0402L]  (hidden comment: CRCW040210K0FKED)
R188  ValueDisplayed: 10.0k  [0402L]  (hidden comment: CRCW040210K0FKED)
R189  ValueDisplayed: 10.0k  [0402L]  (hidden comment: CRCW040210K0FKED)
R190  ValueDisplayed: 1.00k  [0402L]  (hidden comment: CRCW04021K00FKED)
R191  ValueDisplayed: 100k  [0402L]  (hidden comment: CRCW0402100KFKED)
U16  APS12808L-OBMX-BA  [FP-APS12808L-OBMX-BA_BGA24-IPC_C]

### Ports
OSPI1_PSRAM (out, harness OSPI)

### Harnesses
OSPI: OSPI_CLK, OSPI_CSN0, OSPI_DQS, OSPI_ECC_FAIL, OSPI_D[7..0], OSPI_RSTN

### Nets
GND: C184.2 C185.2 C186.2 C187.2 R190.1 R191.1 U16.B3(VSS) U16.C1(VSSQ) U16.E5(VSSQ)
VSYS_1V8: C184.1 C185.1 C186.1 C187.1 R66.2 R67.2 R68.2 R69.2 R70.2 R71.2 R72.2 R73.2 R187.2 R188.2 R189.2 U16.B4(VDD) U16.D1(VDDQ) U16.E4(VDDQ)
OSPI1_CLK: R189.1 R191.2 U16.B2(CLK) ; port OSPI1_PSRAM.OSPI_CLK
OSPI1_CSN0: R83.1 R188.1 U16.A3(~{CE}) ; port OSPI1_PSRAM.OSPI_CSN0
OSPI1_D0: R66.1 R74.1
OSPI1_D1: R67.1 R75.1
OSPI1_D2: R68.1 R76.1
OSPI1_D3: R69.1 R77.1
OSPI1_D4: R70.1 R78.1
OSPI1_D5: R71.1 R79.1
OSPI1_D6: R72.1 R80.1
OSPI1_D7: R73.1 R81.1
OSPI1_DQS: R82.1 R187.1 R190.2 ; port OSPI1_PSRAM.OSPI_DQS
OSPI1_RSTN: U16.A4(~{RST}) ; port OSPI1_PSRAM.OSPI_RSTN
NetR74_2: R74.2 U16.D3(ADQ0)
NetR75_2: R75.2 U16.D2(ADQ1)
NetR76_2: R76.2 U16.C4(ADQ2)
NetR77_2: R77.2 U16.D4(ADQ3)
NetR78_2: R78.2 U16.D5(ADQ4)
NetR79_2: R79.2 U16.E3(ADQ5)
NetR80_2: R80.2 U16.E2(ADQ6)
NetR81_2: R81.2 U16.E1(ADQ7)
NetR82_2: R82.2 U16.C3(DQS/DM)
NetR83_2: R83.2 U16.C2(RFU)

Not connected (* = marked no-connect by the designer): U16 A2(NC)* A5(NC)* B1(NC)* B5(NC)* C5(NC)*

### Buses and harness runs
bus OSPI1_D[7..0]

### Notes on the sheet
- AM261x OSPI1 Memory PSRAM
- OSPI PSRAM

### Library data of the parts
C184-C186 = CMP-0006228-2: as C145-C150 on sheet TIDA-010973_JTAG_UART
C187 = CMP-0078624-1: CAP, CERM, 10 µF, 6.3 V,+/- 20%, X5R, 0402; Manufacturer: MuRata; SizeAreaWB_mm2: 3; SizeArea_mm2: 0.5; AEC Qualified: N; AEC Category: Q200; Value: 10uF; TaMax_C: 85°C; SizeZ_mm: 0.6; TaMin_C: -55°C; U/M: EA; SizeX_mm: 1; Cap_Case: 0402
R66 R67 R69-R73 = CMP-0027732-1: RES, 49.9 k, 1%, 0.05 W, 0201; Manufacturer: Yageo America; Power_W: 50mW; TempCo: 200 ppm/C; Value_Code: 49k9; U/M: EA; Value: 49.9k; EIA_Code: E96; SizeX_mm: 0.6; SizeY_mm: 0.3; SizeZ_mm: 0.26; Value2: 0.05W; SizeArea_mm2: 0.18; AEC Qualified: N; VDC_V: 25V; AEC Category: Q200
R68 = CMP-0027280-3: RES, 4.70 k, 1%, 0.05 W, 0201; Manufacturer: Vishay-Dale; Power_W: 50mW; TempCo: 100 ppm/C; Value_Code: 4k70; Value: 4.70k; Res_ohm: 4.7k; SizeX_mm: 0.6; SizeY_mm: 0.3; SizeZ_mm: 0.33; Value2: 0.05W; SizeArea_mm2: 0.18; AEC Qualified: N; VDC_V: 30V; AEC Category: Q200
R74-R82 = CMP-0027074-3: as R226 on sheet TIDA-010973_JTAG_UART
R83 = CMP-0027008-4: RES, 0, 5%, 0.05 W, 0201; Manufacturer: Vishay-Dale; Power_W: 50mW; TempCo: ppm/C; Value_Code: 0000; Value: 0; EIA_Code: E24; SizeX_mm: 0.6; SizeY_mm: 0.3; SizeZ_mm: 0.26; Value2: 0.05W; SizeArea_mm2: 0.18; AEC Qualified: N; AEC Category: Q200
R187-R189 = CMP-0025958-3: as R164 on sheet TIDA-010973_JTAG_UART
R190 = CMP-0026071-3: as R151 on sheet TIDA-010973_JTAG_UART
R191 = CMP-0025950-3: RES, 100 k, 1%, 0.063 W, AEC-Q200 Grade 0, 0402; Manufacturer: Vishay-Dale; Power_W: 63mW; TempCo: 100 ppm/C; Value: 100k; EIA_Code: E96; SizeX_mm: 1; SizeY_mm: 0.5; SizeZ_mm: 0.6; Value2: 0.063W; AEC Qualified: Y; VDC_V: 50V; AEC Category: Q200; AEC Grade: 0
U16 = CMP-0122758-1: DRAM IoT RAM 128Mb OPI (x8) DDR 200MHz, 1.8V, Ext. Temp., BGA24; Manufacturer: AP Memory; SizeZ_mm: 1.2mm; AEC Qualified: No; Interface: SPI; Max Supply Voltage: 1.98V; Memory Size: 128Mbits; Min Supply Voltage: 1.62V; Nominal Supply Current: 4-22mA; Standoff Height: 0.25mm

## Sheet TIDA-010973_BootConfig.SchDoc
size 431 x 279 mm; Date: Not shown in title block; ApprovedBy: Not shown in title block; CheckedBy: Not shown in title block; Author: Not shown in title block; CompanyName: Not shown in title block; Engineer: Not shown in title block; Organization: Not shown in title block; Address1: Not shown in title block; Address2: Not shown in title block; Address3: Not shown in title block; Address4: Not shown in title block; DocumentNumber: 2; Revision: Use project parameter SCH_Rev; SheetNumber: 12; SheetTotal: 15; PageSetup: Record=PageOptions¦CenterHorizontal=True¦CenterVertical=True¦PrintScale=1.00¦XCorrection=1.00¦YCorrection=1.00¦PrintKind=0¦BorderSize=5000000¦LeftOffset=0¦BottomOffset=0¦Orientation=2¦PaperLength=1000¦PaperWidth=1000¦Scale=100¦PaperSource=15¦PrintQuality=600¦MediaType=1¦DitherType=10¦PaperKind=Letter¦PrintScaleMode=1
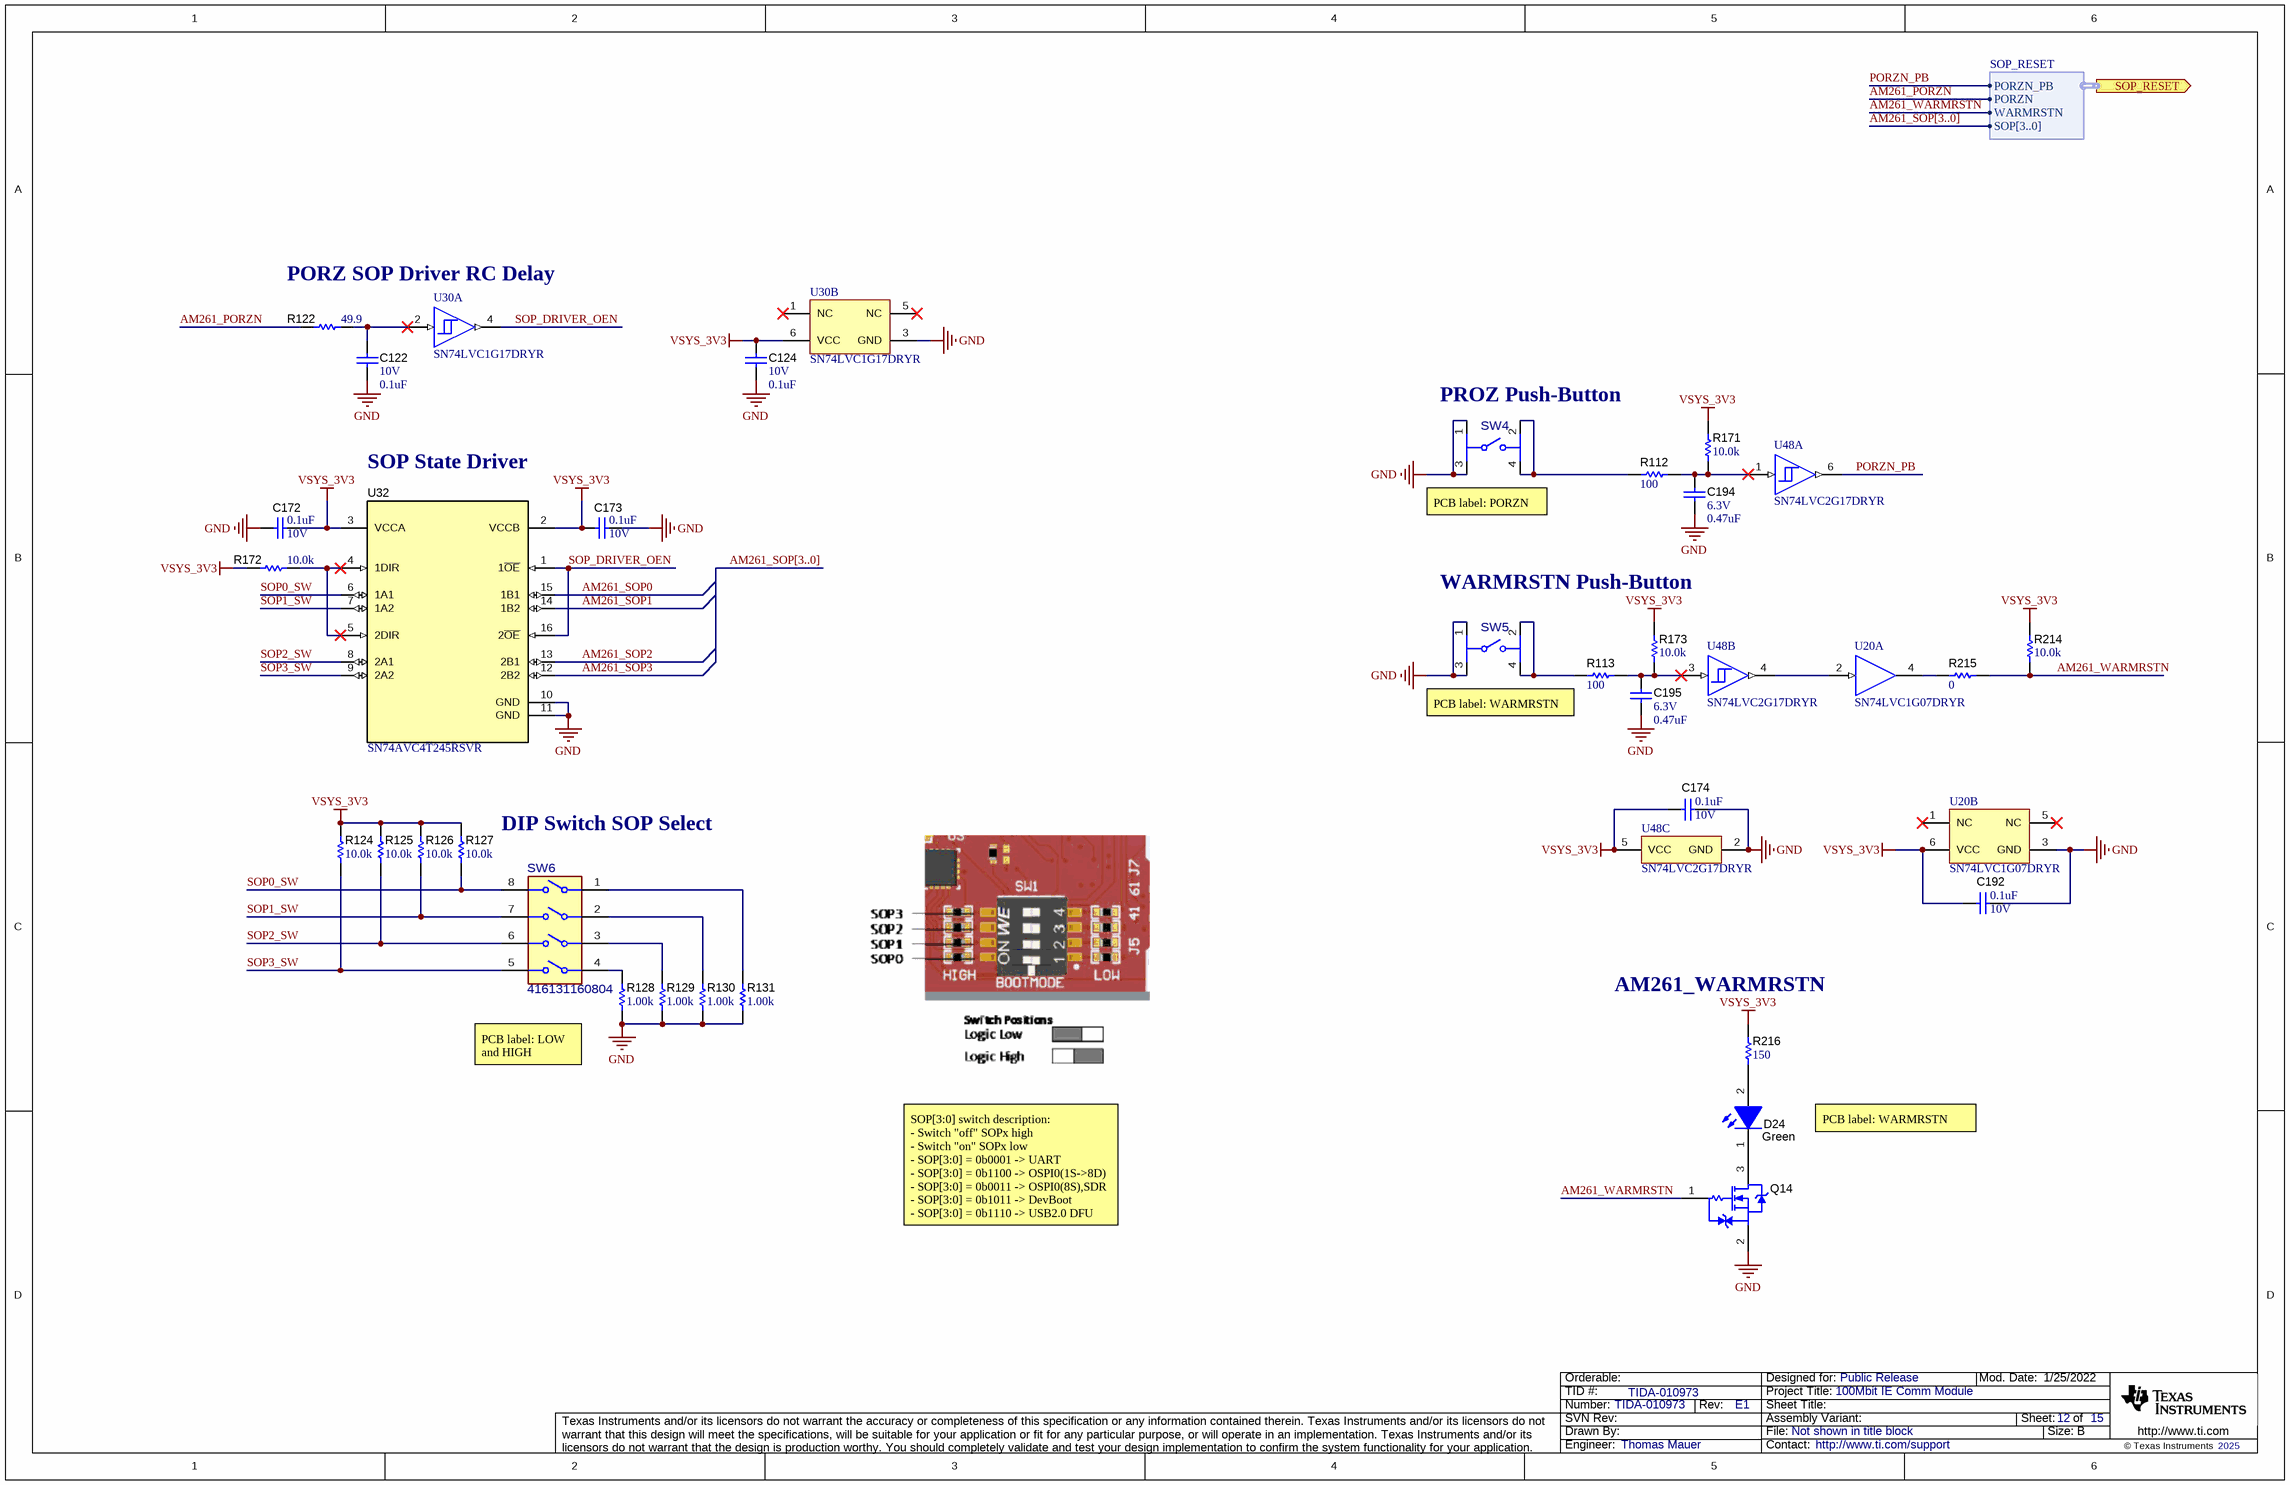
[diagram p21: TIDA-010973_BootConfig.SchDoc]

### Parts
C122  VDC_V: 10V  ValueDisplayed: 0.1uF  [0402L]  (hidden comment: 885012105010)
C124  VDC_V: 10V  ValueDisplayed: 0.1uF  [0402L]  (hidden comment: 885012105010)
C172  VDC_V: 10V  ValueDisplayed: 0.1uF  [0402L]  (hidden comment: 885012105010)
C173  VDC_V: 10V  ValueDisplayed: 0.1uF  [0402L]  (hidden comment: 885012105010)
C174  VDC_V: 10V  ValueDisplayed: 0.1uF  [0402L]  (hidden comment: 885012105010)
C192  VDC_V: 10V  ValueDisplayed: 0.1uF  [0402L]  (hidden comment: 885012105010)
C194  VDC_V: 6.3V  ValueDisplayed: 0.47uF  [0402L]  (hidden comment: 04026D474KAT2A)
C195  VDC_V: 6.3V  ValueDisplayed: 0.47uF  [0402L]  (hidden comment: 04026D474KAT2A)
D24  value Green  [WL-SMCW_GREEN]  (hidden comment: 150060VS75000)
Q14  CSD13383F4  [YJC0003A]  (value not drawn)
R112  ValueDisplayed: 100  [0402L]  (hidden comment: CRCW0402100RFKED)
R113  ValueDisplayed: 100  [0402L]  (hidden comment: CRCW0402100RFKED)
R122  ValueDisplayed: 49.9  [0402L]  (hidden comment: CRCW040249R9FKED)
R124  ValueDisplayed: 10.0k  [0402L]  (hidden comment: CRCW040210K0FKED)
R125  ValueDisplayed: 10.0k  [0402L]  (hidden comment: CRCW040210K0FKED)
R126  ValueDisplayed: 10.0k  [0402L]  (hidden comment: CRCW040210K0FKED)
R127  ValueDisplayed: 10.0k  [0402L]  (hidden comment: CRCW040210K0FKED)
R128  ValueDisplayed: 1.00k  [0402L]  (hidden comment: CRCW04021K00FKED)
R129  ValueDisplayed: 1.00k  [0402L]  (hidden comment: CRCW04021K00FKED)
R130  ValueDisplayed: 1.00k  [0402L]  (hidden comment: CRCW04021K00FKED)
R131  ValueDisplayed: 1.00k  [0402L]  (hidden comment: CRCW04021K00FKED)
R171  ValueDisplayed: 10.0k  [0402L]  (hidden comment: CRCW040210K0FKED)
R172  ValueDisplayed: 10.0k  [0402L]  (hidden comment: CRCW040210K0FKED)
R173  ValueDisplayed: 10.0k  [0402L]  (hidden comment: CRCW040210K0FKED)
R214  ValueDisplayed: 10.0k  [0402L]  (hidden comment: CRCW040210K0FKED)
R215  ValueDisplayed: 0  [0402L]  (hidden comment: CRCW04020000Z0ED)
R216  ValueDisplayed: 150  [0402L]  (hidden comment: CRCW0402150RFKED)
SW4  434351045816  [FP-434351045816_SMT_SW_4MM7_4MM5-MFG]  (value not drawn)
SW5  434351045816  [FP-434351045816_SMT_SW_4MM7_4MM5-MFG]  (value not drawn)
SW6  416131160804  [FP-416131160804_SMT_SW-MFG]
U20  SN74LVC1G07DRYR  [DRY0006A]  (parts A,B of 2)
U30  SN74LVC1G17DRYR  [DRY0006A]  (parts A,B of 2)
U32  SN74AVC4T245RSVR  [RSV0016A]
U48  SN74LVC2G17DRYR  [DRY0006A]  (parts A,B,C of 3)

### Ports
SOP_RESET (out, harness SOP_RESET)

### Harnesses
SOP_RESET: SOP[3..0], PORZN_PB, PORZN, WARMRSTN

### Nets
GND: C122.2 C124.2 C172.1 C173.1 C174.1 C192.1 C194.2 C195.2 Q14.2(S) R128.1 R129.1 R130.1 R131.1 SW4.1 SW4.3 SW5.1 SW5.3 U20.3(GND) U30.3(GND) U32.10(GND) U32.11(GND) U48.2(GND)
VSYS_3V3: C124.1 C172.2 C173.2 C174.2 C192.2 R124.2 R125.2 R126.2 R127.2 R171.2 R172.2 R173.2 R214.2 R216.2 U20.6(VCC) U30.6(VCC) U32.2(VCCB) U32.3(VCCA) U48.5(VCC)
AM261_PORZN: R122.1 ; port SOP_RESET.PORZN
AM261_SOP0: U32.15(1B1)
AM261_SOP1: U32.14(1B2)
AM261_SOP2: U32.13(2B1)
AM261_SOP3: U32.12(2B2)
AM261_WARMRSTN: Q14.1(G) R214.1 R215.2 ; port SOP_RESET.WARMRSTN
PORZN_PB: U48.6(1Y) ; port SOP_RESET.PORZN_PB  [project net PORZ_PB]
SOP0_SW: R127.1 SW6.8 U32.6(1A1)
SOP1_SW: R126.1 SW6.7 U32.7(1A2)
SOP2_SW: R125.1 SW6.6 U32.8(2A1)
SOP3_SW: R124.1 SW6.5 U32.9(2A2)
SOP_DRIVER_OEN: U30.4(Y) U32.1(1~{OE}) U32.16(2~{OE})
NetC122_1: C122.1 R122.2 U30.2(A)
NetC194_1: C194.1 R112.2 R171.1 U48.1(1A)
NetC195_1: C195.1 R113.2 R173.1 U48.3(2A)
NetD24_1: D24.1(K) Q14.3(D)
NetD24_2: D24.2(A) R216.1
NetR112_1: R112.1 SW4.2 SW4.4
NetR113_1: R113.1 SW5.2 SW5.4
NetR128_2: R128.2 SW6.4
NetR129_2: R129.2 SW6.3
NetR130_2: R130.2 SW6.2
NetR131_2: R131.2 SW6.1
NetR172_1: R172.1 U32.4(1DIR) U32.5(2DIR)
NetR215_1: R215.1 U20.4(Y)
NetU20_2: U20.2(A) U48.4(2Y)

Not connected (* = marked no-connect by the designer): U20 1(NC)* 5(NC)*; U30 1(NC)* 5(NC)*

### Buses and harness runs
bus AM261_SOP[3..0]

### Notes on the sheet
- PORZ SOP Driver RC Delay
- (near SW4) PROZ Push-Button
- SOP State Driver
- (near SW4) PCB label: PORZN
- WARMRSTN Push-Button
- (near R113) PCB label: WARMRSTN
- DIP Switch SOP Select
- (near R216) AM261_WARMRSTN
- PCB label: LOW and HIGH
- PCB label: WARMRSTN
- SOP[3:0] switch description:
  - Switch "off" SOPx high
  - Switch "on" SOPx low
  - SOP[3:0] = 0b0001 -> UART
  - SOP[3:0] = 0b1100 -> OSPI0(1S->8D)
  - SOP[3:0] = 0b0011 -> OSPI0(8S),SDR
  - SOP[3:0] = 0b1011 -> DevBoot
  - SOP[3:0] = 0b1110 -> USB2.0 DFU

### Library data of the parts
C122 C124 C172-C174 C192 = CMP-0006221-2: CAP, CERM, 0.1 uF, 10 V, +/- 20%, X5R, 0402; Manufacturer: Wurth Elektronik; TaMin_C: -55°C; Polarized: N; SizeAreaWB_mm2: 3; Value1: Unknown; U/M: EA; Value: 0.1uF; TaMax_C: 85°C; SizeZ_mm: 0.6; SizeX_mm: 1; SizeY_mm: 0.5; Cap_Case: 0402; Cap_F: 100nF; AEC Category: Q200
C194 C195 = CMP-0006199-2: CAP, CERM, 0.47 uF, 6.3 V, +/- 10%, X5R, 0402; Manufacturer: AVX; TaMin_C: -55°C; Polarized: N; SizeAreaWB_mm2: 3; Value1: Unknown; U/M: EA; Value: 0.47uF; TaMax_C: 85°C; SizeZ_mm: 0.6; SizeX_mm: 1; SizeY_mm: 0.5; Cap_Case: 0402; Cap_F: 470nF; AEC Category: Q200
D24 = CMP-0002894-2: as D20 on sheet TIDA-010973_JTAG_UART
Q14 = CMP-0000198-1: MOSFET, N-CH, 12 V, 2.9 A, YJC0003A (PICOSTAR-3); Alternate Manufacturer: None; Manufacturer: Texas Instruments; SizeZ_mm: 0.35; ChType: N; Value2: 2 nC; Value1: 0.04; VdsMax_V: 12V; SizeX_mm: 1.035; SizeY_mm: 0.635; Vgs_V: 10V; Value: 12V; Rdson45_ohm: 0.044; SizeArea_mm2: 0.657225; AEC Category: Q101; IdsMax_A: 2.9A; SizeAreaWB_mm2: 3.327225; U/M: EA; QgTyp_nC: 2
R112 R113 = CMP-0025951-3: as R146 on sheet TIDA-010973_JTAG_UART
R122 = CMP-0026404-2: as R163 on sheet TIDA-010973_JTAG_UART
R124-R127 R171-R173 R214 = CMP-0025958-3: as R164 on sheet TIDA-010973_JTAG_UART
R128-R131 = CMP-0026071-3: as R151 on sheet TIDA-010973_JTAG_UART
R215 = CMP-0026822-3: as R145 on sheet TIDA-010973_JTAG_UART
R216 = CMP-0026022-3: RES, 150, 1%, 0.063 W, AEC-Q200 Grade 0, 0402; Manufacturer: Vishay-Dale; Power_W: 63mW; TempCo: 100 ppm/C; Value_Code: 150R; Value: 150; EIA_Code: E96; SizeX_mm: 1; SizeY_mm: 0.5; SizeZ_mm: 0.6; Value2: 0.063W; AEC Qualified: Y; VDC_V: 50V; AEC Category: Q200; AEC Grade: 0
SW4 SW5 = CMP-0093456-1: Tactile Switch SPST-NO Side Actuated Surface Mount, Right Angle; Manufacturer: Wurth Electronics; Operating Force: 160gf; SizeZ_mm: 1.75mm; AEC Qualified: No; Electromechanical Life: 200000Cycles; VDC_V: 12V; Contact Current Rating: 50mA; Coil Resistance_ohm: 100mΩ
SW6 = CMP-0093176-1: Dip Switch SPST 4 Position Surface Mount Slide (Standard) Actuator 25mA 24VDC; Manufacturer: Wurth; PositionCount: 4; Electromechanical Life: 1000Cycles; Circuit: 4PST; Coil Resistance_ohm: 100mΩ; VDC_V: 24V; Standoff Height: 0mm; SizeZ_mm: 2.65mm; AEC Qualified: No
U20 = CMP-0051412-4: Single Buffer/Driver With Open-Drain Output, DRY0006A (USON-6); Manufacturer: Texas Instruments; Output Type: CMOS; Bits(#): 1; Input Type: CMOS/TTL; Technology Family: LVC; Schmitt Trigger: No; VCC(Max)(V): 5.5; Rating: Catalog; Output Drive (IOL/IOH)(Max)(mA): 32/-32; ICC @ Nom Voltage(Max)(mA): 0.01; VCC(Min)(V): 1.65; F @ Nom Voltage(Max)(Mhz): 150; Logic: True; Voltage(Nom)(V): 1.8,2.5,3.3,5; tpd @ Nom Voltage(Max)(ns): 8.6,6,4.7,4; AEC Category: Q200; AEC Qualified: N; CompType: IC; SizeAreaWB_mm2: 4.9; SizeArea_mm2: 1.45; SizeX_mm: 1.0; SizeZ_mm: 0.6
U30 = CMP-0051441-4: Single Schmitt-Trigger Buffer, DRY0006A (USON-6); Manufacturer: Texas Instruments; Output Type: CMOS; Bits(#): 1; Input Type: CMOS/TTL; Technology Family: LVC; Schmitt Trigger: Yes; 3-State Output: No; VCC(Max)(V): 5.5; Rating: Catalog; Output Drive (IOL/IOH)(Max)(mA): 32/-32; ICC @ Nom Voltage(Max)(mA): 0.01; VCC(Min)(V): 1.65; F @ Nom Voltage(Max)(Mhz): 150; Logic: True; Voltage(Nom)(V): 1.8,2.5,3.3,5; tpd @ Nom Voltage(Max)(ns): 11,6.5,5.5,5; AEC Category: Q200; AEC Qualified: N; CompType: IC; SizeAreaWB_mm2: 4.9; SizeArea_mm2: 1.45; SizeX_mm: 1.0; SizeZ_mm: 0.6
U32 = CMP-0066450-2: 4-Bit Dual-Supply Bus Transceiver with Configurable Voltage-Level Shifting and 3-State Outputs, RSV0016A (UQFN-16); Alternate Manufacturer: Texas Instruments; SizeAreaWB_mm2: 10.08; SizeZ_mm: 0.55; SizeX_mm: 1.8; SizeY_mm: 2.6; SizeArea_mm2: 4.68; CompType: IC; AEC Category: Q200; AEC Qualified: N
U48 = CMP-0051903-4: Dual Schmitt-Trigger Buffer, DRY0006A (USON-6); Manufacturer: Texas Instruments; Output Type: CMOS; Bits(#): 2; Input Type: CMOS/TTL; Technology Family: LVC; Schmitt Trigger: Yes; 3-State Output: No; VCC(Max)(V): 5.5; Rating: Catalog; Output Drive (IOL/IOH)(Max)(mA): 32/-32; ICC @ Nom Voltage(Max)(mA): 0.01; VCC(Min)(V): 1.65; F @ Nom Voltage(Max)(Mhz): 150; Logic: True; Voltage(Nom)(V): 1.8,2.5,3.3,5; tpd @ Nom Voltage(Max)(ns): 9.3,5.7,5.4,4.3; AEC Category: Q200; AEC Qualified: N; CompType: IC; SizeAreaWB_mm2: 4.9; SizeArea_mm2: 1.45; SizeX_mm: 1.0; SizeZ_mm: 0.6

## Sheet TIDA-010973_Hardware.SchDoc
size 431 x 279 mm; Date: Not shown in title block; ApprovedBy: Not shown in title block; CheckedBy: Not shown in title block; Author: Not shown in title block; CompanyName: Not shown in title block; Engineer: Not shown in title block; Organization: Not shown in title block; Address1: Not shown in title block; Address2: Not shown in title block; Address3: Not shown in title block; Address4: Not shown in title block; DocumentNumber: 3; Revision: Use project parameter SCH_Rev; SheetNumber: 15; SheetTotal: 15; PageSetup: Record=PageOptions¦CenterHorizontal=True¦CenterVertical=True¦PrintScale=1.00¦XCorrection=1.00¦YCorrection=1.00¦PrintKind=0¦BorderSize=5000000¦LeftOffset=0¦BottomOffset=0¦Orientation=2¦PaperLength=1000¦PaperWidth=1000¦Scale=100¦PaperSource=15¦PrintQuality=600¦MediaType=1¦DitherType=10¦PaperKind=Letter¦PrintScaleMode=1
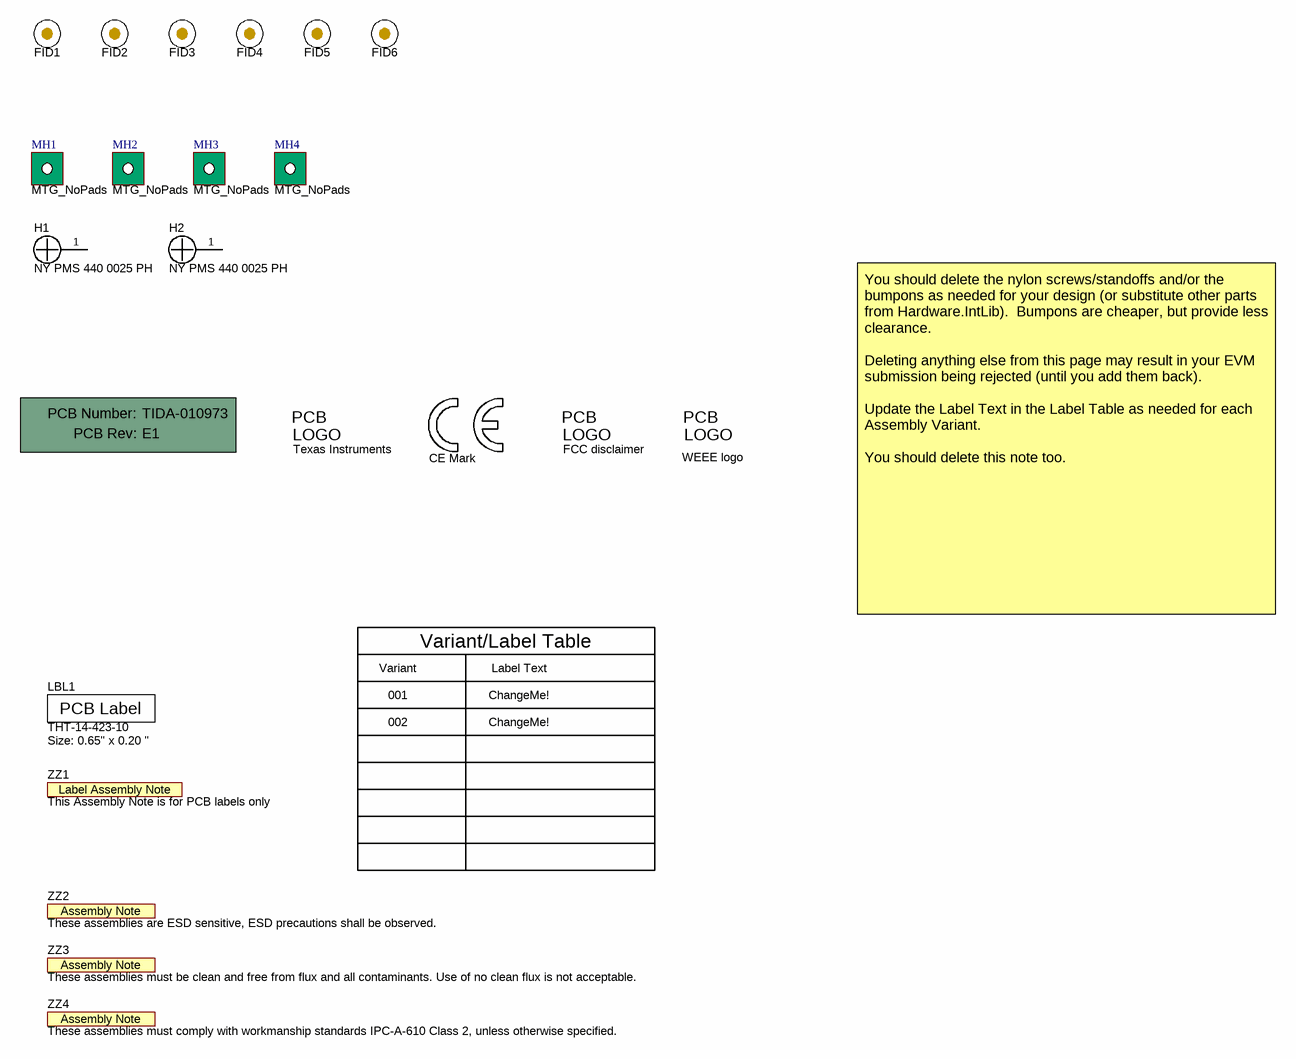
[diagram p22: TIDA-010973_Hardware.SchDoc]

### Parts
!PCB  Printed Circuit Board  (value not drawn)  (mechanical)
FID1  Fiducial  [Fiducial10-20]  (value not drawn)
FID2  Fiducial  [Fiducial10-20]  (value not drawn)
FID3  Fiducial  [Fiducial10-20]  (value not drawn)
FID4  Fiducial  [Fiducial10-20]  (value not drawn)
FID5  Fiducial  [Fiducial10-20]  (value not drawn)
FID6  Fiducial  [Fiducial10-20]  (value not drawn)
H1  NY PMS 440 0025 PH  [NY PMS 440 0025 PH]
H2  NY PMS 440 0025 PH  [NY PMS 440 0025 PH]
LBL1  THT-14-423-10  Note: Size: 0.65" x 0.20 "  [Label_650x200]
Logo1  Texas Instruments  [TI_Stacked_Overlay_Small]  (no BOM)
Logo2  CE Mark  [CE_Mark_5mm]  (no BOM)
Logo3  FCC disclaimer  [FCC_disclaimer]  (no BOM)
Logo4  WEEE logo  [WEEE_Minimum]  (no BOM)
MH1  MTG_NoPads  [NPTH125mil]  (no BOM)
MH2  MTG_NoPads  [NPTH125mil]  (no BOM)
MH3  MTG_NoPads  [NPTH125mil]  (no BOM)
MH4  MTG_NoPads  [NPTH125mil]  (no BOM)
ZZ1  This Assembly Note is for PCB labels only  [AssemblyNoteLabel]  (no BOM)
ZZ2  These assemblies are ESD sensitive, ESD precautions shall be observed.  [AssemblyNote]  (no BOM)
ZZ3  These assemblies must be clean and free from flux and all contaminants. Use of no clean flux is not acceptable.  [AssemblyNote]  (no BOM)
ZZ4  These assemblies must comply with workmanship standards IPC-A-610 Class 2, unless otherwise specified.  [AssemblyNote]  (no BOM)

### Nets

Not connected (* = marked no-connect by the designer): H1 1; H2 1

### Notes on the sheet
- Variant
- Variant/Label Table
- Label Text
- You should delete the nylon screws/standoffs and/or the bumpons as needed for your design (or substitute other parts from Hardware.IntLib).  Bumpons are cheaper, but provide less clearance.
  Deleting anything else from this page may result in your EVM submission being rejected (until you add them back).
  Update the Label Text in the Label Table as needed for each Assembly Variant.
  You should delete this note too.
- 001
- 002
- ChangeMe!

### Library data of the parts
!PCB = CMP-0003618-2: Manufacturer: Any; PartNumber: TIDA-010973
FID1-FID6 = CMP-0077181-1: Fiducial mark.  There is nothing to buy or mount.
H1 H2 = CMP-0003617-1: Machine Screw, Round, #4-40 x 1/4, Nylon, Philips panhead; Manufacturer: B&F Fastener Supply; CompType: Hardware
LBL1 = CMP-0003625-1: Thermal Transfer Printable Labels, 0.650" W x 0.200" H - 10,000 per roll; Manufacturer: Brady; CompType: Label
Logo1 = CMP-0074838-1: Texas Instrument Corporate Signature; SymbolCreator: a0412235; Lib Reference: TI_Logo; Library Reference: Logo
Logo2 = CMP-0074844-2: Manufacturer: Texas Instruments; SymbolCreator: a0412235; AEC Category: Q200; CompType: IC
Logo3 = CMP-0074847-1: FCC_disclaimer; Library Reference: Logo
Logo4 = CMP-0074769-4: Manufacturer: Texas Instruments; CompType: IC; AEC Category: Q200
MH1-MH4 = CMP-0078424-2: PCB Mounting Hole, No Pad; Manufacturer: Any; Key: Mounting Hole (non-standard) No Pad
ZZ1 = CMP-0003616-3
ZZ2 = CMP-0077236-1
ZZ3 = CMP-0077237-1
ZZ4 = CMP-0077238-1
